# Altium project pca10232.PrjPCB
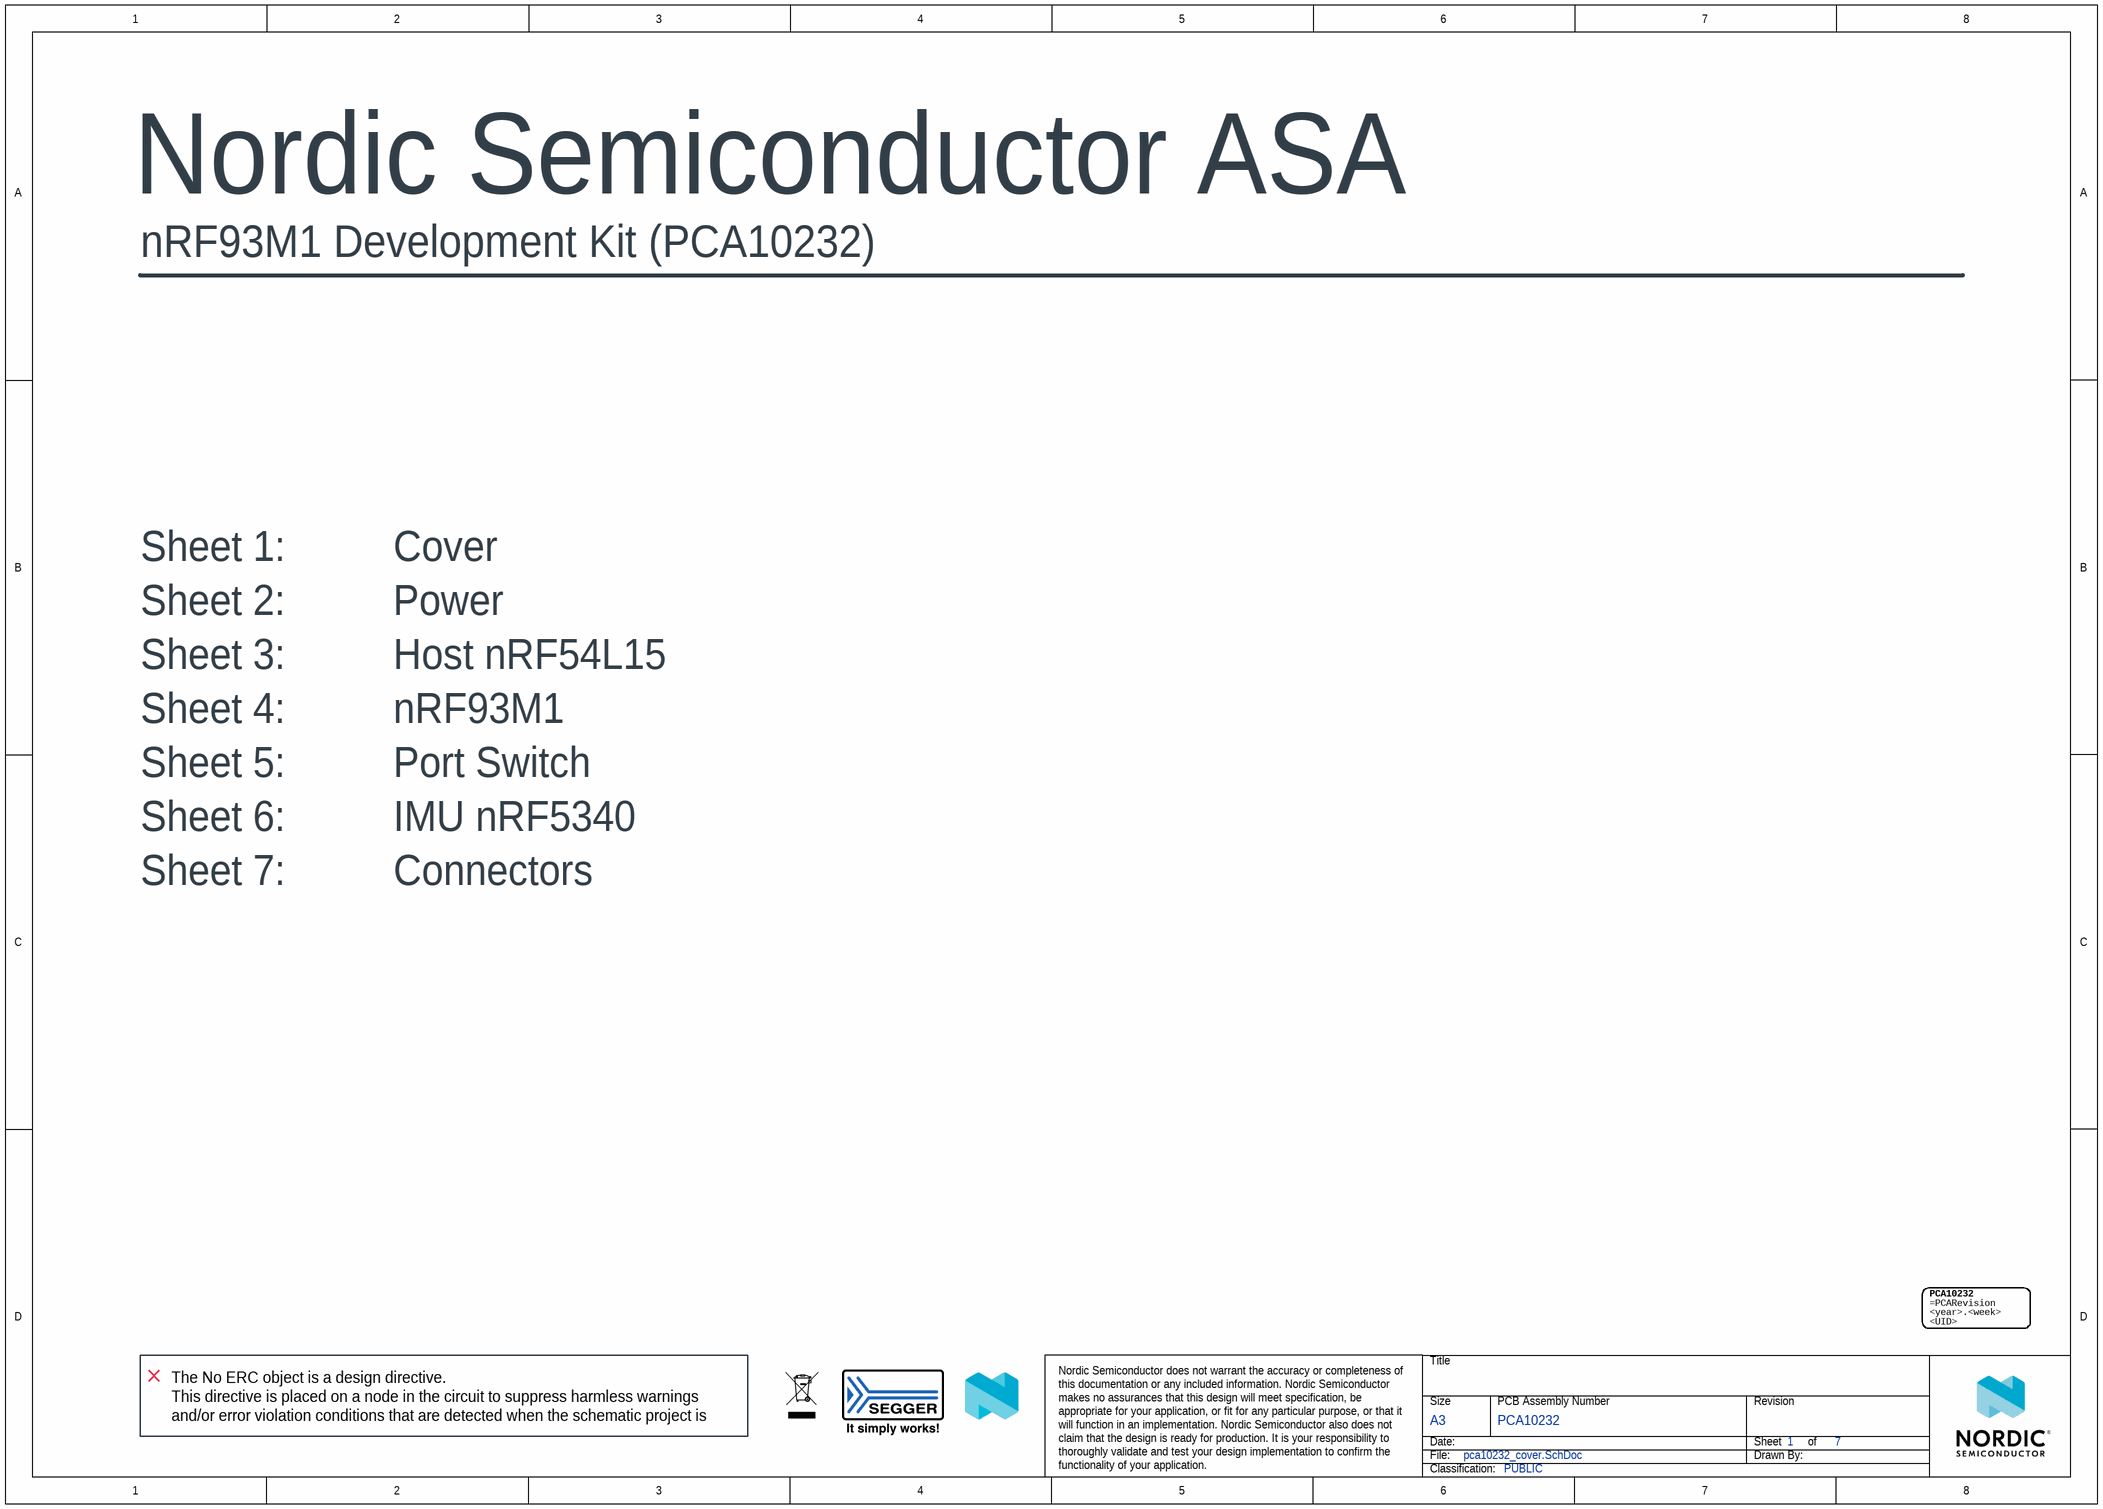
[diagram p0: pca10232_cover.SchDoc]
BoardThickness: 1.6mm; BoardTitle: nRF93M1 Development Kit; Classification: PUBLIC; Compliance: RoHS, REACH, Halogen-Free; Designer: Nordic Semiconductor; Dielectric: FR-4; NrOfLayers: 6; Organization: Nordic Semiconductor; PCAName: PCA10232; PCARevision: 0.4.0; PCBNumber: 401074; PCBRevision: 0.4.0; PCBStackup: 6001; ProductName: nRF93M1 Development Kit; ProjectName: nRF93M1; SilkscreenColor: White; SoldermaskColor: Blue; SurfaceFinish: ENIG Gold
7 sheets, 241 parts. Net scope: flat (ports and power ports of the same name join across sheets).
Board file: 401074.PcbDoc
Sheets:
  pca10232_cover.SchDoc
  pca10232_power.SchDoc
  pca10232_host_nrf54l15.SchDoc
  pca10232_nrf93m1.SchDoc
  pca10232_port_switch.SchDoc
  pca10232_imu_nrf5340.SchDoc
  pca10232_connectors.SchDoc

## Sheet pca10232_cover.SchDoc: =BoardTitle + ' - Cover'
size A3; Organization: Nordic Semiconductor; DocumentNumber: 1; Revision: 0.4.0; SheetNumber: 1; SheetTotal: 7; Author: Nordic Semiconductor; CompanyName: Nordic Semiconductor; DrawnBy: Nordic Semiconductor; DocumentSize: A3

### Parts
LABEL1  Solderbridge  [LabelSilk_15x40]  (value not drawn)  (graphical)
LOGO1  WEE Symbol  [WEEE_3x4.5mm]  (value not drawn)  (no BOM)
LOGO2  Segger Logo S  [logo]  (value not drawn)  (no BOM)
LOGO3  Solderbridge  [NORDIC_LOGO_LYING]  (value not drawn)  (graphical)

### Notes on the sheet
- Sheet 1:          Cover
- Sheet 2:          Power
- Sheet 3:          Host nRF54L15
- Sheet 4:          nRF93M1
- Sheet 5:          Port Switch
- Sheet 6:          IMU nRF5340
- Sheet 7:          Connectors
- The No ERC object is a design directive.
  This directive is placed on a node in the circuit to suppress harmless warnings and/or error violation conditions that are detected when the schematic project is compiled.

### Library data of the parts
LABEL1 = Label_15x40: PCA version label, stick-on, 15x40mm
LOGO1 = WEEE Symbol 3x4.5mm: WEEE Directive symbol; Manufacturer: N.A.
LOGO2 = Segger Logo S: Segger logo, small size; Manufacturer: N.A.
LOGO3 = Nordic Logo lying

## Sheet pca10232_power.SchDoc: =BoardTitle + ' - Power'
size A3; Organization: Nordic Semiconductor; DocumentNumber: 2; Revision: 0.4.0; SheetNumber: 2; SheetTotal: 7; Author: Nordic Semiconductor; CompanyName: Nordic Semiconductor; DrawnBy: Nordic Semiconductor; DocumentSize: A3
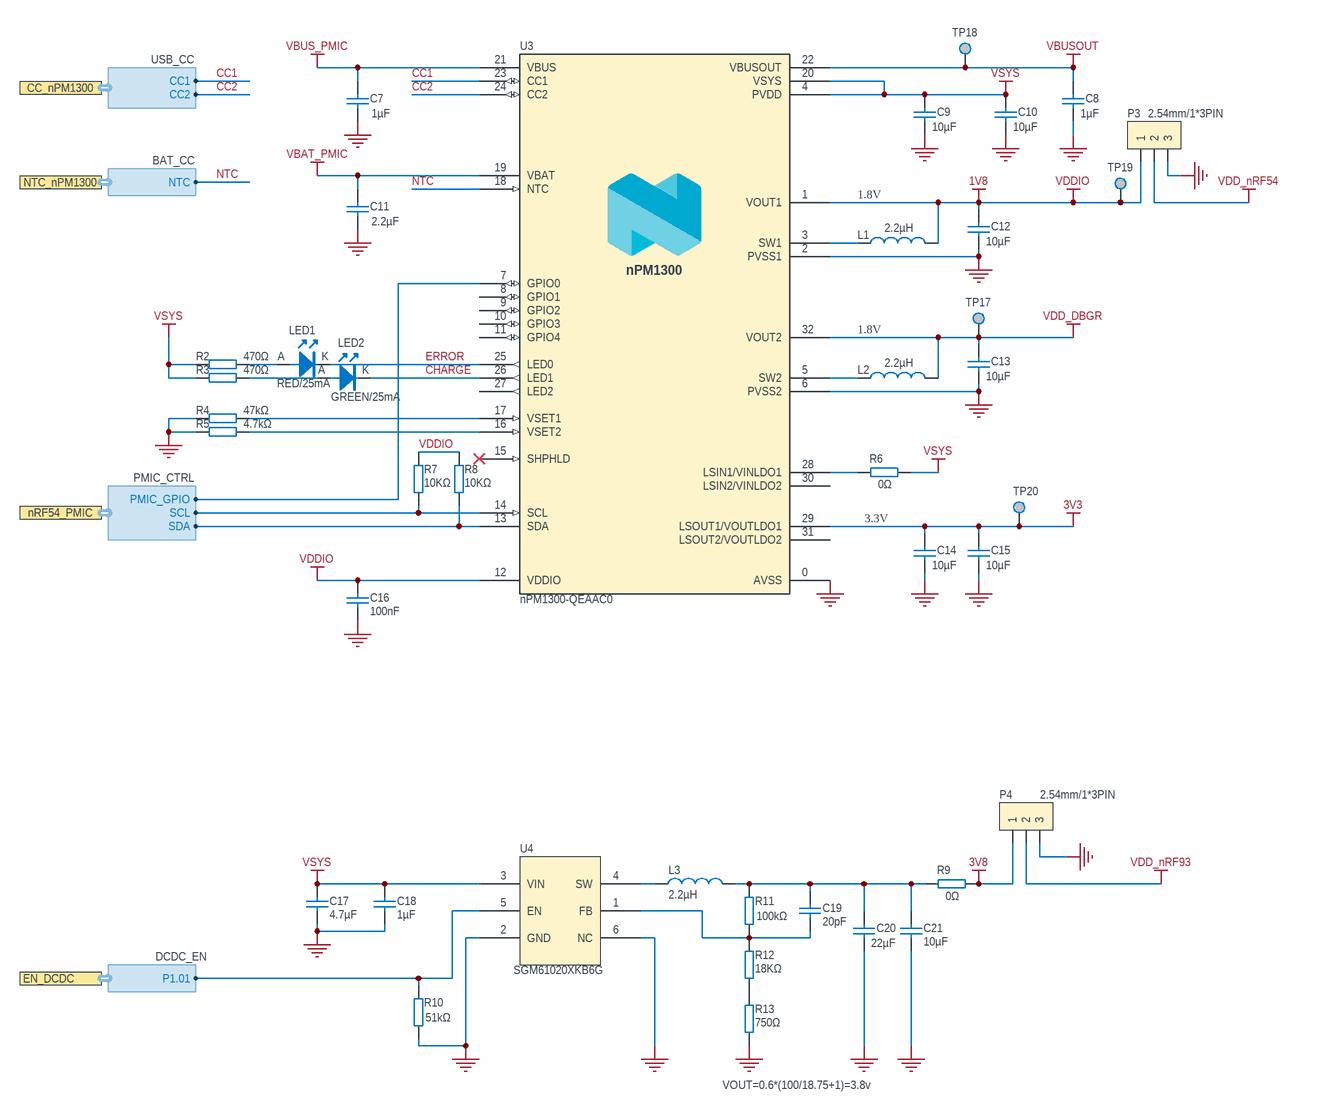
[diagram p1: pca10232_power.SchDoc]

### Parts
C7  1µF  [0402C_0.4D]
C8  1µF  [0402C_0.4D]
C9  10µF  [0603C_0.6D]
C10  10µF  [0603C_0.6D]
C11  2.2µF  [0402C_0.4D]
C12  10µF  [0603C_0.6D]
C13  10µF  [0603C_0.6D]
C14  10µF  [0603C_0.6D]
C15  10µF  [0603C_0.6D]
C16  100nF  [0201_0.25D]
C17  4.7µF  [0402C_0.4D]
C18  1µF  [0402C_0.4D]
C19  20pF  [0201_0.25D]
C20  22µF  [0603C_0.6D]
C21  10µF  [0402C_0.4D]
L1  2.2µH  [SKFB160808-2R2M]
L2  2.2µH  [SKFB160808-2R2M]
L3  2.2µH  [0805L_0.7D-NB]
LED1  RED/25mA  [D0402]
LED2  GREEN/25mA  [D0402]
P3  2.54mm/1*3PIN  [SIP 2.54_3_S]
P4  2.54mm/1*3PIN  [SIP 2.54_3_S]
R2  470Ω  [0402R_0.4D]
R3  470Ω  [0402R_0.4D]
R4  47kΩ  [0201_0.25D]
R5  4.7kΩ  [0201_0.25D]
R6  0Ω  [0402R_0.4D]
R7  10KΩ  [0201_0.25D]
R8  10KΩ  [0201_0.25D]
R9  0Ω  [0402R_0.4D]
R10  51kΩ  [0201_0.25D]
R11  100kΩ  [0201_0.25D]
R12  18KΩ  [0201_0.25D]
R13  750Ω  [0201_0.25D]
TP17  Testpoint  [test]  (value not drawn)  (no BOM)
TP18  Testpoint  [test]  (value not drawn)  (no BOM)
TP19  Testpoint  [test]  (value not drawn)  (no BOM)
TP20  Testpoint  [test]  (value not drawn)  (no BOM)
U3  nPM1300-QEAAC0  [QFN32(0.5)-5X5]
U4  SGM61020XKB6G  [SOT-563-6]

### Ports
CC_nPM1300 (harness USB_CC), EN_DCDC (harness DCDC_EN), nRF54_PMIC (harness PMIC_CTRL), NTC_nPM1300 (harness BAT_CC)

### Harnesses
USB_CC: CC1, CC2
BAT_CC: NTC
DCDC_EN: P1.01
PMIC_CTRL: SCL, SDA, PMIC_GPIO

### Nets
1V8: C12.2 C16.2 L1.2 P3.1 R7.2 R8.1 TP19.1 U3.1(VOUT1) U3.12(VDDIO)  [also labelled VDDIO]
3V3: C14.2 C15.2 TP20.1 U3.29(LSOUT1/VOUTLDO1)
3V8: P4.1 R9.2
GND: C7.1 C8.1 C9.1 C10.1 C11.1 C12.1 C13.1 C14.1 C15.1 C16.1 C17.1 C18.1 C20.1 C21.1 P3.3 P4.3 R4.1 R5.1 R10.1 R13.1 U3.0(AVSS) U3.2(PVSS1) U3.6(PVSS2) U4.2(GND) U4.6(NC)
VBAT_PMIC: C11.2 U3.19(VBAT)
VBUS_PMIC: C7.2 U3.21(VBUS)
VBUSOUT: C8.2 TP18.1 U3.22(VBUSOUT)
VDD_DBGR: C13.2 L2.2 TP17.1 U3.32(VOUT2)
VDD_nRF54: P3.2
VDD_nRF93: P4.2
VSYS: C9.2 C10.2 C17.2 C18.2 R2.1 R3.1 R6.2 U3.4(PVDD) U3.20(VSYS) U4.3(VIN)
CC1: U3.23(CC1) ; port CC_nPM1300.CC1
CC2: U3.24(CC2) ; port CC_nPM1300.CC2
CHARGE: LED2.K U3.26(LED1)
ERROR: LED1.K U3.25(LED0)
NTC: U3.18(NTC) ; port NTC_nPM1300.NTC
P1.01/XL2: R10.2 U4.5(EN) ; port EN_DCDC.P1.01
P1.11: R7.1 U3.14(SCL) ; port nRF54_PMIC.SCL
P1.14: R8.2 U3.13(SDA) ; port nRF54_PMIC.SDA
NetC19_1: C19.1 R11.1 R12.2 U4.1(FB)
NetC19_2: C19.2 C20.2 C21.2 L3.2 R9.1 R11.2
NetL1_1: L1.1 U3.3(SW1)
NetL2_1: L2.1 U3.5(SW2)
NetL3_1: L3.1 U4.4(SW)
NetLED1_A: LED1.A R2.2
NetLED2_A: LED2.A R3.2
NetR4_2: R4.2 U3.17(VSET1)
NetR5_2: R5.2 U3.16(VSET2)
NetR6_1: R6.1 U3.28(LSIN1/VINLDO1)
NetR12_1: R12.1 R13.2
NetSB3_2: U3.7(GPIO0) ; port nRF54_PMIC.PMIC_GPIO

Not connected (* = marked no-connect by the designer): U3 8(GPIO1) 9(GPIO2) 10(GPIO3) 11(GPIO4) 15(SHPHLD)* 27(LED2) 30(LSIN2/VINLDO2) 31(LSOUT2/VOUTLDO2)

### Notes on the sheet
- (near L1) 1.8V
- (near L2) 1.8V
- 3.3V
- (near R13) VOUT=0.6*(100/18.75+1)=3.8v

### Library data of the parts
C7 C8 = 1405002135: 1uF/25V/10%/X5R; Manufacturer Part Number: CL05A105KA5NQNC; Manufacturer: Samsung
C9 C10 C12-C15 = 1405005588: 10uF/25V/20%/X5R; Manufacturer Part Number: CC0603MRX5R8BB106; Manufacturer: Yageo
C11 = 1405005857: 2.2uF/16V/10%/X5R; Manufacturer Part Number: V225K0402X5R160NNT; Manufacturer: Viiyong
C16 = 1405001080: 0.1uF/10V/10%/X5R; Manufacturer Part Number: 0201X104K100CT; Manufacturer: Walsin
C17 = 1405002483: 4.7uF/16V/20%/X5R; Manufacturer Part Number: CL05A475MO5NUNC; Manufacturer: Samsung
C18 = 1405004038: 1uF/16V/10%/X5R; Manufacturer Part Number: CL05A105KO5NNNC; Manufacturer: Samsung
C19 = 1405004304: 20pF/50V/5%/C0G; Manufacturer Part Number: V200J0201C0G500NAT; Manufacturer: Viiyong
C20 = 1405001346: 22uF/10V/20%/X5R; Manufacturer Part Number: CL10A226MP8NUN#; Manufacturer: Samsung
C21 = 1405001308: 10uF/10V/20%/X5R; Manufacturer Part Number: CL05A106MP5NUNC; Manufacturer: Samsung
L1 L2 = 1404000234: 2.2uH/20%/2.5*2*1.2/2.07A/0.166Ω; Manufacturer Part Number: SWPA252012S2R2MT; Manufacturer: Sunlord
L3 = 1404002926: 2.2uH/20%/2.0*1.2*0.8/1.7A/146mΩ; Manufacturer Part Number: SKFB201208PA2R2M; Manufacturer: Scientic
LED1 = 1409000384: 25mA/40mcd; Manufacturer Part Number: 16-213SURC/S530-A3/TR8; Manufacturer: Everlight
LED2 = 1409003070: 25mA/112-225mcd; Manufacturer Part Number: 16-213/GHC-YR1S1N/3T; Manufacturer: Everlight
P3 P4 = 1416001241: Manufacturer Part Number: CNT-M254-1*3-GS-6/3-01
R2 R3 = 1408000316: 470Ω/5%; Manufacturer Part Number: RC0402JR-07470RL; Manufacturer: Yageo
R4 = 1408001835: 47KΩ/1%; Manufacturer Part Number: RC0201FR-0747KL; Manufacturer: Yageo
R5 = 1408002588: 4.7KΩ/1%; Manufacturer Part Number: 0201WMF4701TEE; Manufacturer: Uniohm
R6 R9 = 1408001258: 0Ω/1%; Manufacturer Part Number: RC0402FR-070RL; Manufacturer: Yageo
R7 R8 = 1408001391: 10KΩ/1%; Manufacturer Part Number: RC0201FR-0710KL; Manufacturer: Yageo
R10 = 1408006147: 51K/5%; Manufacturer Part Number: RJ0201-51K; Manufacturer: Uniohm
R11 = 1408002571: 100KΩ/1%; Manufacturer Part Number: 0201WMF1003TEE; Manufacturer: Uniohm
R12 = 1408006619: 18KΩ/1%; Manufacturer Part Number: RC0201FR-0718KL; Manufacturer: Yageo
R13 = 1408006619_1: 750Ω/1%; Manufacturer: Yageo
TP17-TP20 = MARK: Manufacturer Part Number: N.A.
U3 = nPM1300-QEAAC0: Li-Ion/Li-Polymer USB-C battery charger with high efficiency buck regulators, LDOs or load switches, LED drivers, TWI and VBUSOUT; Manufacturer: Nordic Semiconductor
U4 = SGM61020XKB6G/TR: Manufacturer: SG Micro

## Sheet pca10232_host_nrf54l15.SchDoc: =BoardTitle + ' - Host nRF54L15'
size A3; Organization: Nordic Semiconductor; DocumentNumber: 3; Revision: 0.4.0; SheetNumber: 3; SheetTotal: 7; Author: Nordic Semiconductor; CompanyName: Nordic Semiconductor; DrawnBy: Nordic Semiconductor; DocumentSize: A3
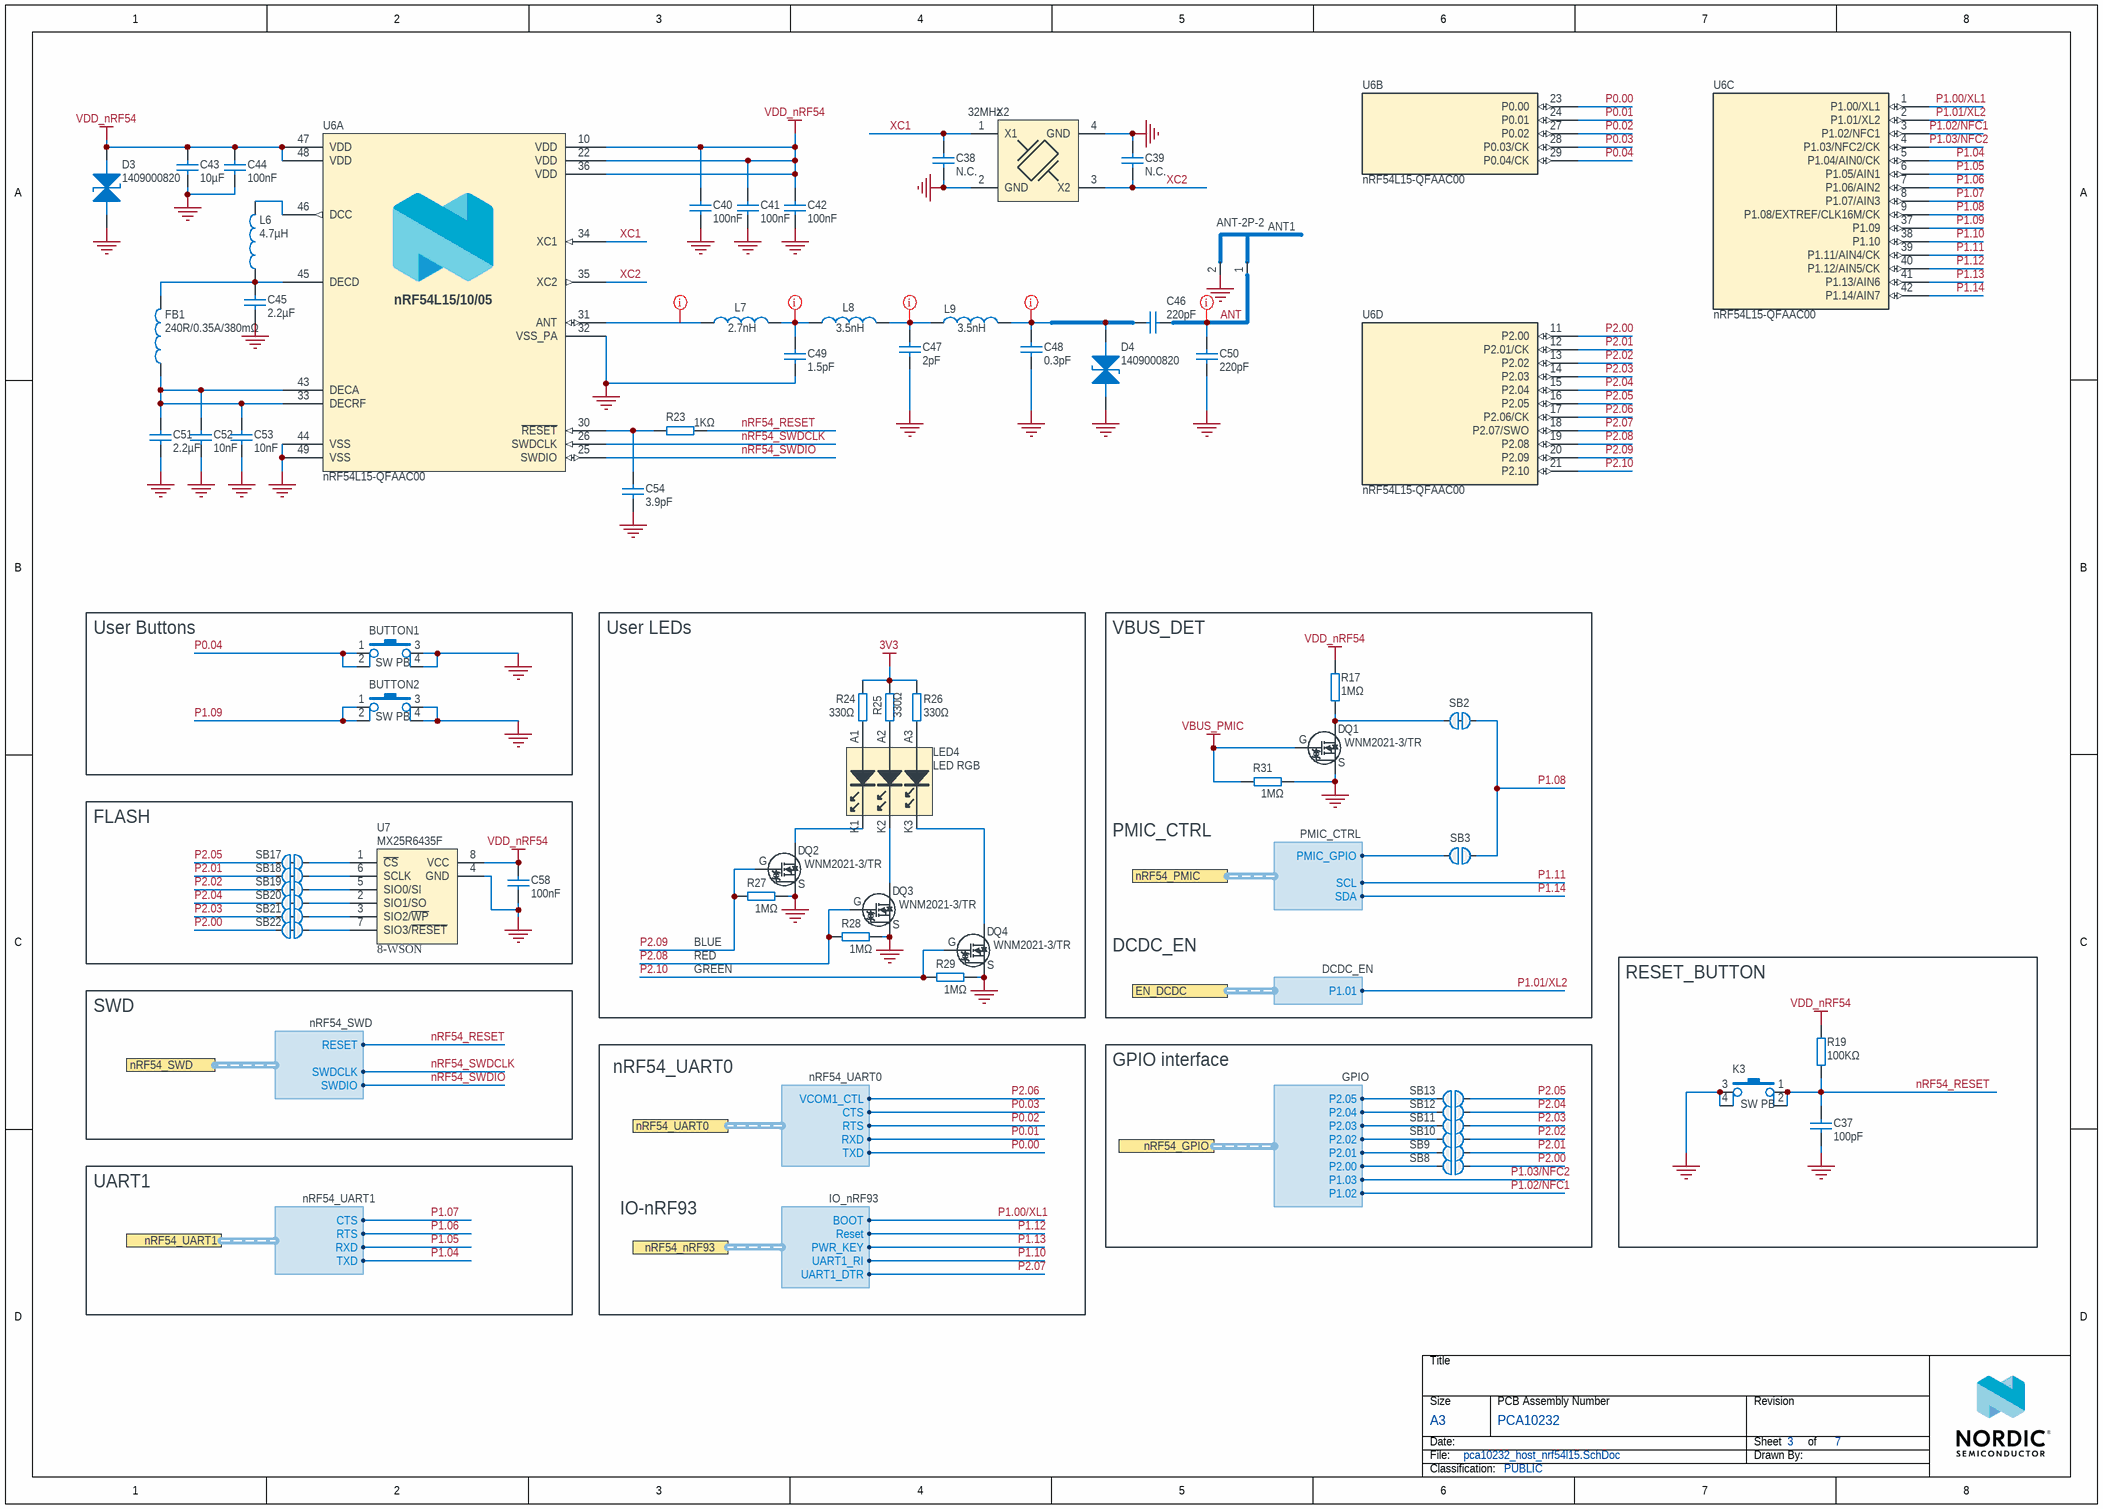
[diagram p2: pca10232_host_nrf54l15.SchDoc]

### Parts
ANT1  ANT-2P-2  [ANT_PCB]  (no BOM)
BUTTON1  SW PB  [SW-4.2X3.35-4P-S]
BUTTON2  SW PB  [SW-4.2X3.35-4P-S]
C37  100pF  [0402C_0.4D]
C38  N.C.  [0201_0.25D]
C39  N.C.  [0201_0.25D]
C40  100nF  [0201_0.25D]
C41  100nF  [0201_0.25D]
C42  100nF  [0201_0.25D]
C43  10µF  [0402C_0.4D-NB]
C44  100nF  [0201_0.25D]
C45  2.2µF  [0201_0.25D]
C46  220pF  [0201C_0.2D(NB)]
C47  2pF  [0201_0.25D]
C48  0.3pF  [0201_0.25D]
C49  1.5pF  [0201_0.25D]
C50  220pF  [0201C_0.2D(NB)]
C51  2.2µF  [0201_0.25D]
C52  10nF  [0201_0.25D]
C53  10nF  [0201_0.25D]
C54  3.9pF  [0201_0.25D]
C58  100nF  [0201_0.25D]
D3  1409000820  [DFN1006]
D4  1409000820  [D0201-NP]
FB1  240R/0.35A/380mΩ  [0201L_0.2D(NB)]
K3  SW PB  [SW-4.2X3.35-4P-S]
L6  4.7µH  [0603C_0.6D(RF)]
L7  2.7nH  [0201_0.25D]
L8  3.5nH  [0201_0.25D]
L9  3.5nH  [0201_0.25D]
LED4  LED RGB  [D1616-RGB]
Q1  WNM2021-3/TR  [SOT-323-3G]
Q2  WNM2021-3/TR  [SOT-323-3G]
Q3  WNM2021-3/TR  [SOT-323-3G]
Q4  WNM2021-3/TR  [SOT-323-3G]
R17  1MΩ  [0201_0.25D]
R19  100KΩ  [0201_0.25D]
R23  1KΩ  [0201_0.25D]
R24  330Ω  [0402R_0.4D]
R25  330Ω  [0402R_0.4D]
R26  330Ω  [0402R_0.4D]
R27  1MΩ  [0201_0.25D]
R28  1MΩ  [0201_0.25D]
R29  1MΩ  [0201_0.25D]
R31  1MΩ  [0201_0.25D]
SB2  Solderbridge_Shorted  [Solderbridge_Shorted]  (value not drawn)  (net tie, no BOM)
SB3  Solderbridge  [Solderbridge_NO_Shorted]  (value not drawn)  (no BOM)
SB8  Solderbridge  [Solderbridge_NO_Shorted]  (value not drawn)  (no BOM)
SB9  Solderbridge  [Solderbridge_NO_Shorted]  (value not drawn)  (no BOM)
SB10  Solderbridge  [Solderbridge_NO_Shorted]  (value not drawn)  (no BOM)
SB11  Solderbridge  [Solderbridge_NO_Shorted]  (value not drawn)  (no BOM)
SB12  Solderbridge  [Solderbridge_NO_Shorted]  (value not drawn)  (no BOM)
SB13  Solderbridge  [Solderbridge_NO_Shorted]  (value not drawn)  (no BOM)
SB17  Solderbridge_Shorted  [Solderbridge_Shorted]  (value not drawn)  (net tie, no BOM)
SB18  Solderbridge_Shorted  [Solderbridge_Shorted]  (value not drawn)  (net tie, no BOM)
SB19  Solderbridge_Shorted  [Solderbridge_Shorted]  (value not drawn)  (net tie, no BOM)
SB20  Solderbridge_Shorted  [Solderbridge_Shorted]  (value not drawn)  (net tie, no BOM)
SB21  Solderbridge_Shorted  [Solderbridge_Shorted]  (value not drawn)  (net tie, no BOM)
SB22  Solderbridge_Shorted  [Solderbridge_Shorted]  (value not drawn)  (net tie, no BOM)
U6  nRF54L15-QFAAC00  [nRF54L15_QFN48_6X6_0.4]  (parts A,B,C,D of 4)
U7  MX25R6435F  [WSON8L_6X5_1.27]
X2  32MHz  [2016]

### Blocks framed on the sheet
User Buttons: BUTTON1 BUTTON2
User LEDs: LED4 Q2-Q4 R24-R29
FLASH: C58 SB17-SB22 U7
RESET_BUTTON: C37 K3 R19
GPIO interface: SB8-SB13

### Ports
EN_DCDC (harness DCDC_EN), nRF54_GPIO (harness GPIO), nRF54_nRF93 (harness IO_nRF93), nRF54_PMIC (harness PMIC_CTRL), nRF54_SWD (harness nRF54_SWD), nRF54_UART0 (harness nRF54_UART0), nRF54_UART1 (harness nRF54_UART1)

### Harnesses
nRF54_SWD: SWDIO, SWDCLK, RESET
nRF54_UART0: RTS, CTS, RXD, TXD, VCOM1_CTL
nRF54_UART1: RTS, CTS, RXD, TXD
IO_nRF93: PWR_KEY, Reset, UART1_RI, UART1_DTR, BOOT
GPIO: P1.02, P1.03, P2.00, P2.01, P2.02, P2.03, P2.04, P2.05
PMIC_CTRL: SCL, SDA, PMIC_GPIO
DCDC_EN: P1.01

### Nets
3V3: R24.2 R25.2 R26.2
GND: ANT1.2 BUTTON1.3 BUTTON1.4 BUTTON2.3 BUTTON2.4 C37.1 C38.1 C39.2 C40.1 C41.1 C42.1 C43.1 C44.1 C45.1 C47.1 C48.1 C49.1 C50.1 C51.1 C52.1 C53.1 C54.1 C58.1 D3.A D4.A K3.3 K3.4 Q1.S Q2.S Q3.S Q4.S R27.2 R28.2 R29.2 R31.2 U6.32(VSS_PA) U6.44(VSS) U6.49(VSS) U7.4(GND) U7.9(GND) X2.2(GND) X2.4(GND)
VBUS_PMIC: Q1.G R31.1
VDD_nRF54: C40.2 C41.2 C42.2 C43.2 C44.2 C58.2 D3.K R17.2 R19.2 U6.10(VDD) U6.22(VDD) U6.36(VDD) U6.47(VDD) U6.48(VDD) U7.8(VCC)
ANT: ANT1.1 C46.2 C50.2
nRF54_RESET: C37.2 K3.1 K3.2 R19.1 R23.2 ; port nRF54_SWD.RESET
nRF54_SWDCLK: U6.26(SWDCLK) ; port nRF54_SWD.SWDCLK
nRF54_SWDIO: U6.25(SWDIO) ; port nRF54_SWD.SWDIO
P0.00: U6.23(P0.00) ; port nRF54_UART0.TXD
P0.01: U6.24(P0.01) ; port nRF54_UART0.RXD
P0.02: U6.27(P0.02) ; port nRF54_UART0.RTS
P0.03: U6.28(P0.03/CK) ; port nRF54_UART0.CTS
P0.04: BUTTON1.1 BUTTON1.2 U6.29(P0.04/CK)
P1.00/XL1: U6.1(P1.00/XL1) ; port nRF54_nRF93.BOOT  [project net BOOT]
P1.01/XL2: U6.2(P1.01/XL2) ; port EN_DCDC.P1.01
P1.02/NFC1: U6.3(P1.02/NFC1) ; port nRF54_GPIO.P1.02
P1.03/NFC2: U6.4(P1.03/NFC2/CK) ; port nRF54_GPIO.P1.03
P1.04: U6.5(P1.04/AIN0/CK) ; port nRF54_UART1.TXD
P1.05: U6.6(P1.05/AIN1) ; port nRF54_UART1.RXD
P1.06: U6.7(P1.06/AIN2) ; port nRF54_UART1.RTS
P1.07: U6.8(P1.07/AIN3) ; port nRF54_UART1.CTS
P1.08: SB2.2 SB3.1 U6.9(P1.08/EXTREF/CLK16M/CK)
P1.09: BUTTON2.1 BUTTON2.2 U6.37(P1.09)
P1.10: U6.38(P1.10) ; port nRF54_nRF93.UART1_RI
P1.11: U6.39(P1.11/AIN4/CK) ; port nRF54_PMIC.SCL
P1.12: U6.40(P1.12/AIN5/CK) ; port nRF54_nRF93.Reset
P1.13: U6.41(P1.13/AIN6) ; port nRF54_nRF93.PWR_KEY
P1.14: U6.42(P1.14/AIN7) ; port nRF54_PMIC.SDA
P2.00: SB8.2 SB22.1 U6.11(P2.00)
P2.01: SB9.2 SB18.1 U6.12(P2.01/CK)
P2.02: SB10.2 SB19.1 U6.13(P2.02)
P2.03: SB11.2 SB21.1 U6.14(P2.03)
P2.04: SB12.2 SB20.1 U6.15(P2.04)
P2.05: SB13.2 SB17.1 U6.16(P2.05)
P2.06: U6.17(P2.06/CK) ; port nRF54_UART0.VCOM1_CTL
P2.07: U6.18(P2.07/SWO) ; port nRF54_nRF93.UART1_DTR
P2.08: Q3.G R28.1 U6.19(P2.08)
P2.09: Q2.G R27.1 U6.20(P2.09)
P2.10: Q4.G R29.1 U6.21(P2.10)
XC1: C38.2 U6.34(XC1) X2.1(X1)
XC2: C39.1 U6.35(XC2) X2.3(X2)
NetC45_2: C45.2 FB1.2 L6.1 U6.45(DECD)
NetC46_1: C46.1 C48.2 D4.K L9.2
NetC47_2: C47.2 L8.2 L9.1
NetC49_2: C49.2 L7.2 L8.1
NetC51_2: C51.2 C52.2 C53.2 FB1.1 U6.33(DECRF) U6.43(DECA)
NetC54_2: C54.2 R23.1 U6.30(~{RESET})
NetL6_2: L6.2 U6.46(DCC)
NetL7_1: L7.1 U6.31(ANT)
NetLED4_A1: LED4.A1(A) R24.1
NetLED4_A2: LED4.A2(A) R25.1
NetLED4_A3: LED4.A3(A) R26.1
NetLED4_K1: LED4.K1(K) Q2.D
NetLED4_K2: LED4.K2(K) Q3.D
NetLED4_K3: LED4.K3(K) Q4.D
NetP1_5: SB8.1 ; port nRF54_GPIO.P2.00
NetP2_1: SB9.1 ; port nRF54_GPIO.P2.01
NetP2_2: SB10.1 ; port nRF54_GPIO.P2.02
NetP2_3: SB11.1 ; port nRF54_GPIO.P2.03
NetP2_4: SB12.1 ; port nRF54_GPIO.P2.04
NetP2_5: SB13.1 ; port nRF54_GPIO.P2.05
NetQ1_D: Q1.D R17.1 SB2.1
NetSB3_2: SB3.2 ; port nRF54_PMIC.PMIC_GPIO
NetSB17_2: SB17.2 U7.1(~{CS})
NetSB18_2: SB18.2 U7.6(SCLK)
NetSB19_2: SB19.2 U7.5(SIO0/SI)
NetSB20_2: SB20.2 U7.2(SIO1/SO)
NetSB21_2: SB21.2 U7.3(SIO2/~{WP})
NetSB22_2: SB22.2 U7.7(SIO3/~{RESET})

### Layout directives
net class ANT1: ANT, NetC46_1, NetC47_2, NetC49_2, NetL7_1

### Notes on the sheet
- VBUS_DET
- PMIC_CTRL
- (near U7) 8-WSON
- BLUE
- RED
- GREEN
- DCDC_EN
- SWD
- nRF54_UART0
- UART1
- IO-nRF93

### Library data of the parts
ANT1 = ANT 2P-2: ANT
BUTTON1 BUTTON2 K3 = 1414000721: 3.2*4.2*2.5mm; Manufacturer Part Number: BL-QC-3.2X4.2
C37 = 1405000464: 100pF/16V/10%/X7R; Manufacturer Part Number: CL05B104KO5NNNC; Manufacturer: Samsung
C38 C39 = CAP-NBOM: Manufacturer Part Number: N.A.
C40-C42 C44 C58 = 1405001080: as C16 on sheet pca10232_power
C43 = 1405001308_1: 10uF/10V/20%/X5R; Manufacturer Part Number: CL05A106MP5NUNC; Manufacturer: Samsung
C45 C51 = 1405005059: 2.2uF/10V/20%/X5R; Manufacturer Part Number: V225M0201X5R100NXT; Manufacturer: Viiyong
C46 C50 = 1405002000: 8pF/50V/0.1pF/C0G; Manufacturer Part Number: GRM0335C1H8R0BA01D; Manufacturer: Murata
C47 = 1405002405: 2pF/50V/±0.1pF/GQC; Manufacturer Part Number: V2R0B0201GQC500NAT; Manufacturer: Viiyong
C48 = 1405001154: 0.3pF/50V/±0.1pF/GQC; Manufacturer Part Number: V0R3B0201GQC500NAT; Manufacturer: Viiyong
C49 = 1405002406: 1.5pF/50V/±0.1pF/GQC; Manufacturer Part Number: V1R5B0201GQC500NAT; Manufacturer: Viiyong
C52 C53 = 1405005868: 10nF/25V/10%/X7R; Manufacturer Part Number: V103K0201X7R250NAT; Manufacturer: Viiyong
C54 = 1405002488: 3.9pF/50V/±0.1pF/C0G; Manufacturer Part Number: V3R9B0201C0G500NAT; Manufacturer: Viiyong
D3 = 1409000820_1: 5V/100W
D4 = 1409000820: 5V/100W
FB1 = 1404001917: Manufacturer: Murata
L6 = 1404000149: 0603
L7 = 1404002414: 2.7nH/±0.1nH/500mA/0.2Ω; Manufacturer Part Number: SDCL0603Q2N7BT02B03; Manufacturer: Sunlord
L8 L9 = 1404002487: 3.4nH/±0.1nH/450mA/0.25Ω; Manufacturer Part Number: SDCL0603Q3N4BT02B03; Manufacturer: Sunlord
LED4 = 1409000550: 25mA/100mcd,180mcd, 50mcd; Manufacturer Part Number: 19-337/R6GHBHC-A01/2T; Manufacturer: Everlight
Q1-Q4 = 1412002244: NMOS/20V/0.89A; Manufacturer: Willsemi
R17 R27-R29 R31 = 1408001480: 1MΩ/1%; Manufacturer Part Number: RC0201FR-071ML; Manufacturer: Yageo
R19 = 1408001446: 100KΩ/5%; Manufacturer Part Number: RC0201JR-07100KL; Manufacturer: Yageo
R23 = 1408001445: 1KΩ/5%; Manufacturer Part Number: RC0201JR-071KL; Manufacturer: Yageo
R24-R26 = 1408000315: 330Ω/5%; Manufacturer Part Number: 0402WGJ0331TCE; Manufacturer: Uniohm
SB2 SB17-SB22 = Solderbridge Shorted 0.4mm: Shorted Solderbridge; Manufacturer: N.A.
SB3 SB8-SB13 = Solderbridge 0.4mm: Manufacturer: N.A.
U6 = nRF54L15-QFAAC00: Multi-protocol Bluetooth Low Energy, IEEE 802.15.4 and 2.4GHz proprietary Wireless MCU; Manufacturer: Nordic Semiconductor
U7 = MX25R6435FZNIL0: Ultra low power, 64M-bit, serial multi I/O flash memory; Manufacturer: Macronix
X2 = 1413001678: 8pF/32MHz/10PPM/-40~85℃; Manufacturer Part Number: 9S32000073

## Sheet pca10232_nrf93m1.SchDoc: =BoardTitle + ' - nRF93M1 Cat.1bis'
size A3; Organization: Nordic Semiconductor; DocumentNumber: 4; Revision: 0.4.0; SheetNumber: 4; SheetTotal: 7; Author: Nordic Semiconductor; CompanyName: Nordic Semiconductor; DrawnBy: Nordic Semiconductor; DocumentSize: A3
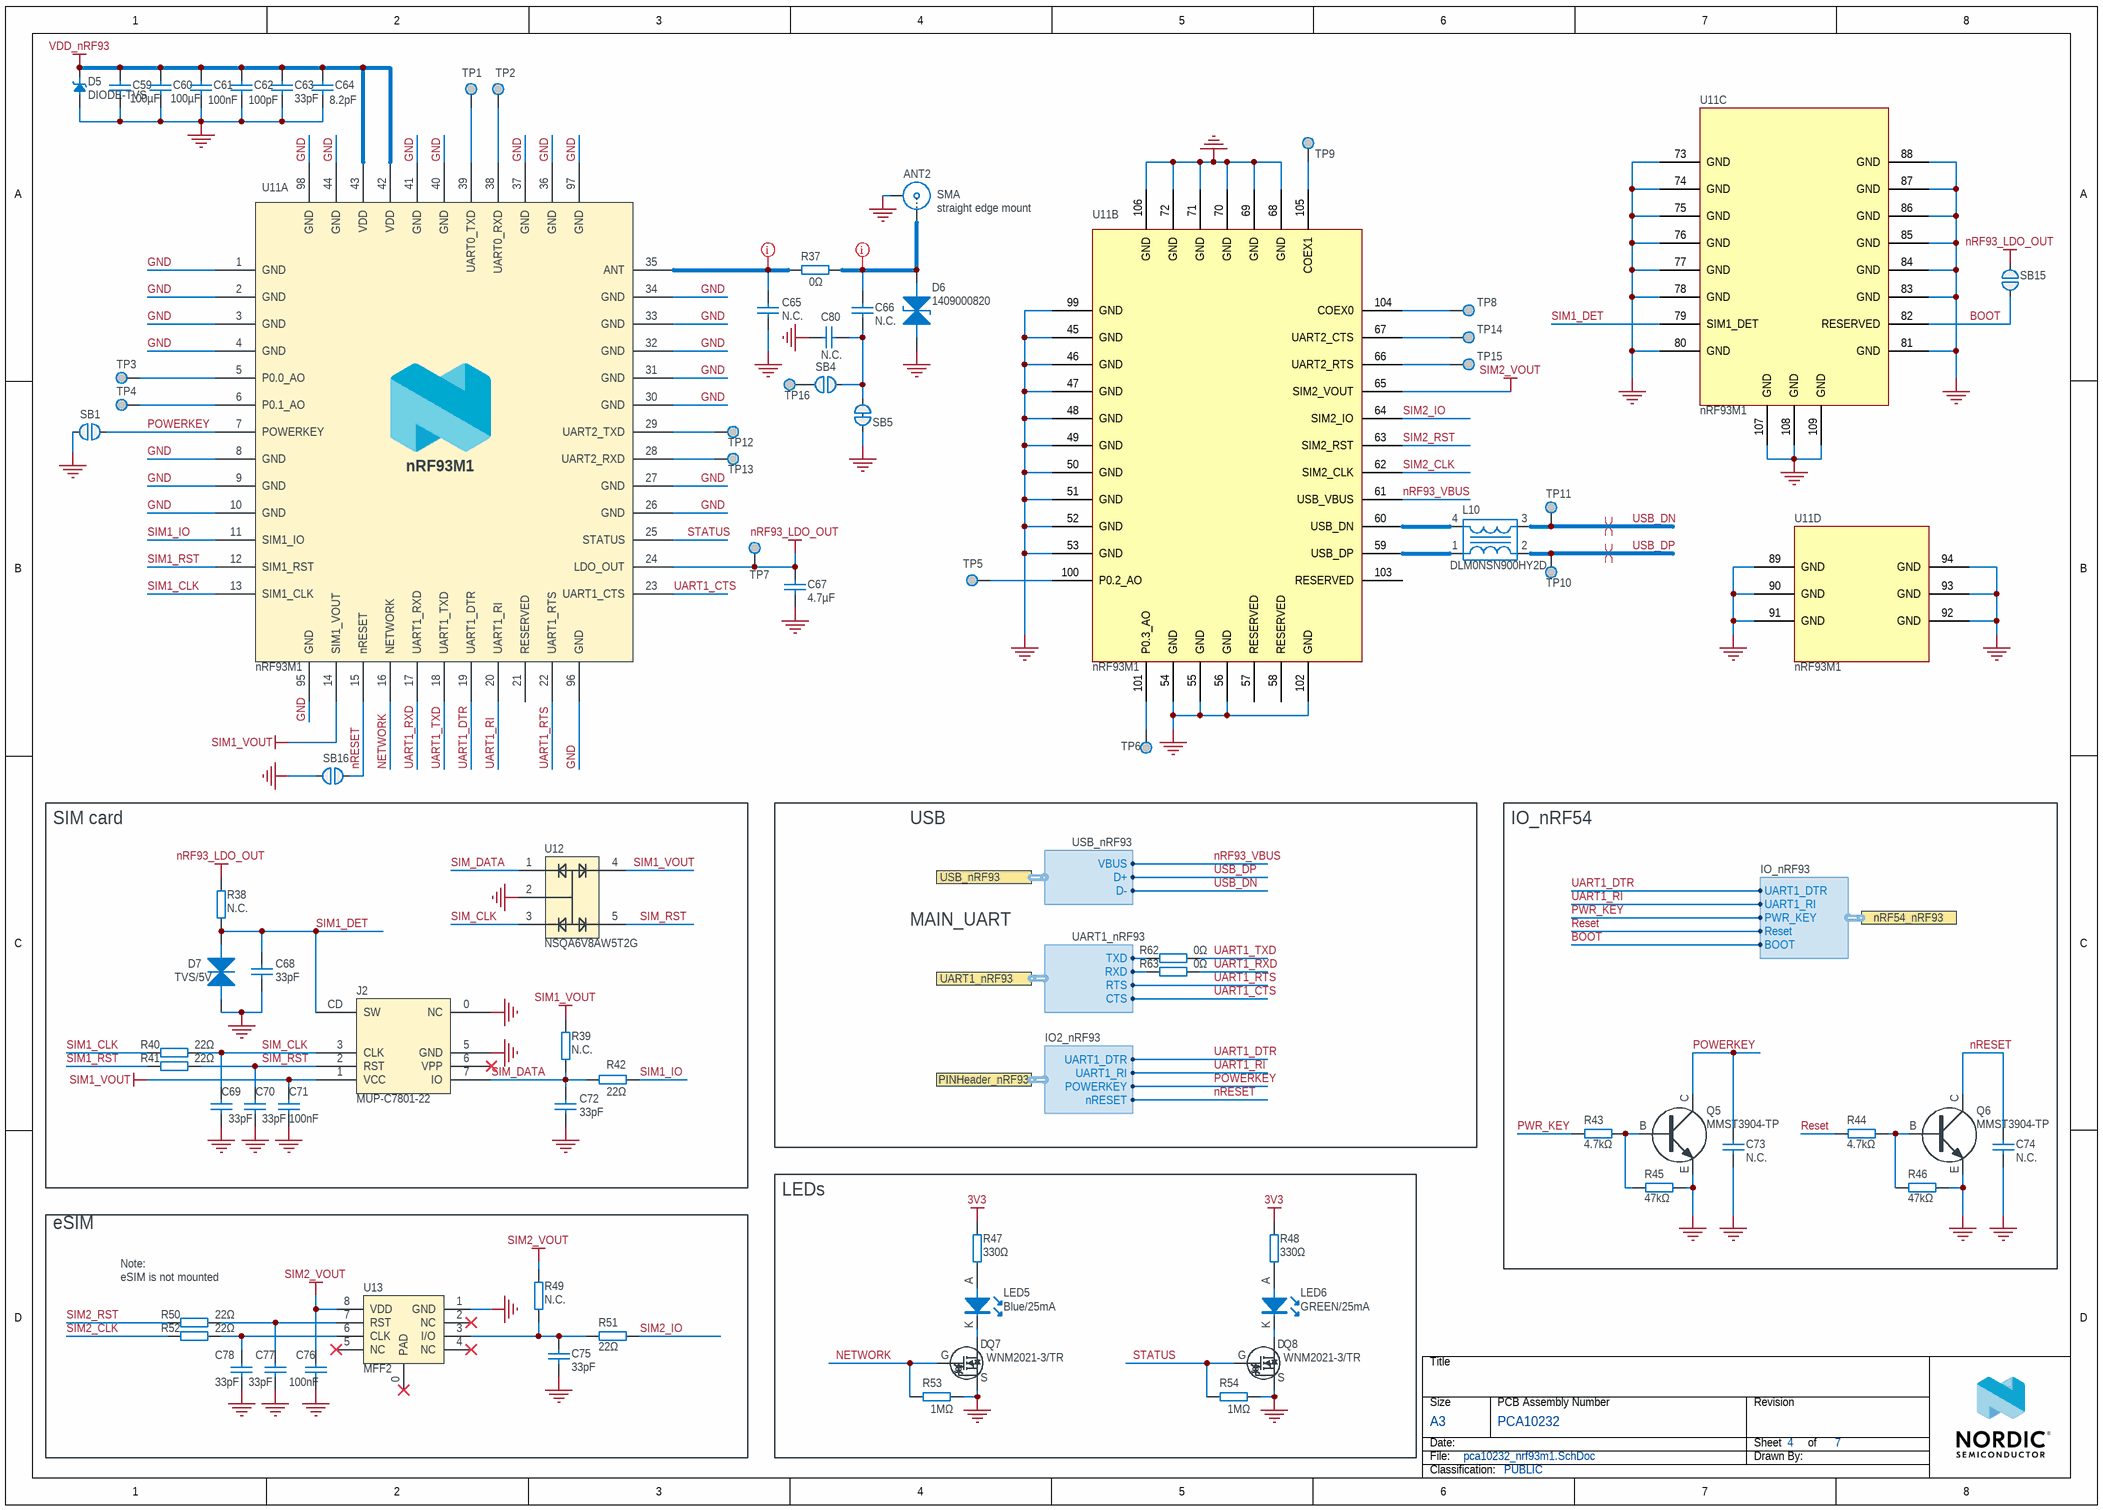
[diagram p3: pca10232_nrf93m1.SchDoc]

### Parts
ANT2  SMA  [SMA-SMD]
C59  100µF  [1206C_1.2D]
C60  100µF  [1206C_1.2D]
C61  100nF  [0201_0.25D]
C62  100pF  [0201_0.25D]
C63  33pF  [0201_0.25D]
C64  8.2pF  [0201_0.25D]
C65  N.C.  [0402C_0.4D]
C66  N.C.  [0402C_0.4D]
C67  4.7µF  [0201_0.25D]
C68  33pF  [0201_0.25D]
C69  33pF  [0201_0.25D]
C70  33pF  [0201_0.25D]
C71  100nF  [0201_0.25D]
C72  33pF  [0201_0.25D]
C73  N.C.  [0201_0.25D]
C74  N.C.  [0201_0.25D]
C75  33pF  [0201_0.25D]
C76  100nF  [0201_0.25D]
C77  33pF  [0201_0.25D]
C78  33pF  [0201_0.25D]
C80  N.C.  [0402C_0.4D]
D5  DIODE-TVS  [UDFN2(1610)]
D6  1409000820  [D0201-NP]
D7  TVS/5V  [SOD-523-NP]
J2  MUP-C7801-22  [SIM-MUP-C7801]
L10  DLM0NSN900HY2D  [L-0.85X0.65]
LED5  Blue/25mA  [D0402]
LED6  GREEN/25mA  [D0402]
Q5  MMST3904-TP  [SOT-323-3A]
Q6  MMST3904-TP  [SOT-323-3A]
Q7  WNM2021-3/TR  [SOT-323-3G]
Q8  WNM2021-3/TR  [SOT-323-3G]
R37  0Ω  [0402R_0.4D]
R38  N.C.  [0402R_0.4D]
R39  N.C.  [0201_0.25D]
R40  22Ω  [0201_0.25D]
R41  22Ω  [0201_0.25D]
R42  22Ω  [0201_0.25D]
R43  4.7kΩ  [0201_0.25D]
R44  4.7kΩ  [0201_0.25D]
R45  47kΩ  [0201_0.25D]
R46  47kΩ  [0201_0.25D]
R47  330Ω  [0402R_0.4D]
R48  330Ω  [0402R_0.4D]
R49  N.C.  [0201_0.25D]
R50  22Ω  [0201_0.25D]
R51  22Ω  [0201_0.25D]
R52  22Ω  [0201_0.25D]
R53  1MΩ  [0201_0.25D]
R54  1MΩ  [0201_0.25D]
R62  0Ω  [0402R_0.4D]
R63  0Ω  [0402R_0.4D]
SB1  Solderbridge  [Solderbridge_NO_Shorted]  (value not drawn)  (no BOM)
SB4  Solderbridge  [Solderbridge_NO_Shorted]  (value not drawn)  (no BOM)
SB5  Solderbridge_Shorted  [Solderbridge_Shorted]  (value not drawn)  (net tie, no BOM)
SB15  Solderbridge  [Solderbridge_NO_Shorted]  (value not drawn)  (no BOM)
SB16  Solderbridge  [Solderbridge_NO_Shorted]  (value not drawn)  (no BOM)
TP1  Testpoint  [test]  (value not drawn)  (no BOM)
TP2  Testpoint  [test]  (value not drawn)  (no BOM)
TP3  Testpoint  [test]  (value not drawn)  (no BOM)
TP4  Testpoint  [test]  (value not drawn)  (no BOM)
TP5  Testpoint  [test]  (value not drawn)  (no BOM)
TP6  Testpoint  [test]  (value not drawn)  (no BOM)
TP7  Testpoint  [test]  (value not drawn)  (no BOM)
TP8  Testpoint  [test]  (value not drawn)  (no BOM)
TP9  Testpoint  [test]  (value not drawn)  (no BOM)
TP10  Testpoint  [test]  (value not drawn)  (no BOM)
TP11  Testpoint  [test]  (value not drawn)  (no BOM)
TP12  Testpoint  [test]  (value not drawn)  (no BOM)
TP13  Testpoint  [test]  (value not drawn)  (no BOM)
TP14  Testpoint  [test]  (value not drawn)  (no BOM)
TP15  Testpoint  [test]  (value not drawn)  (no BOM)
TP16  Testpoint  [test]  (value not drawn)  (no BOM)
U11  nRF93M1  [nRF93M1]  (parts A,B,C,D of 4)
U12  NSQA6V8AW5T2G  [SOT-323-5]
U13  MFF2  [MFF2]

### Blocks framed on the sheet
SIM card: C68-C72 D7 J2 R38-R42 U12
IO_nRF54: C73 C74 Q5 Q6 R43-R46
LEDs: LED5 LED6 Q7 Q8 R47 R48 R53 R54
eSIM: C75-C78 R49-R52 U13

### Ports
nRF54_nRF93 (harness IO_nRF93), PINHeader_nRF93 (harness IO2_nRF93), UART1_nRF93 (harness UART1_nRF93), USB_nRF93 (harness USB_nRF93)

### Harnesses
USB_nRF93: D+, D-, VBUS
IO_nRF93: PWR_KEY, Reset, UART1_RI, UART1_DTR, BOOT
UART1_nRF93: RTS, CTS, TXD, RXD
IO2_nRF93: POWERKEY, nRESET, UART1_RI, UART1_DTR

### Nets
3V3: R47.2 R48.2
GND: ANT2.2(Y) C59.1 C60.1 C61.1 C62.1 C63.1 C64.1 C65.1 C67.1 C68.2 C69.1 C70.1 C71.1 C72.1 C73.1 C74.1 C75.1 C76.1 C77.1 C78.1 C80.2 D5.A D6.A D7.K J2.0(NC) J2.5(GND) Q5.E Q6.E Q7.S Q8.S R45.2 R46.2 R53.2 R54.2 SB1.1 SB5.1 SB16.1 U11.1(GND) U11.2(GND) U11.3(GND) U11.4(GND) U11.8(GND) U11.9(GND) U11.10(GND) U11.26(GND) U11.27(GND) U11.30(GND) U11.31(GND) U11.32(GND) U11.33(GND) U11.34(GND) U11.36(GND) U11.37(GND) U11.40(GND) U11.41(GND) U11.44(GND) U11.45(GND) U11.46(GND) U11.47(GND) U11.48(GND) U11.49(GND) U11.50(GND) U11.51(GND) U11.52(GND) U11.53(GND) U11.54(GND) U11.55(GND) U11.56(GND) U11.68(GND) U11.69(GND) U11.70(GND) U11.71(GND) U11.72(GND) U11.73(GND) U11.74(GND) U11.75(GND) U11.76(GND) U11.77(GND) U11.78(GND) U11.80(GND) U11.81(GND) U11.83(GND) U11.84(GND) U11.85(GND) U11.86(GND) U11.87(GND) U11.88(GND) U11.89(GND) U11.90(GND) U11.91(GND) U11.92(GND) U11.93(GND) U11.94(GND) U11.95(GND) U11.96(GND) U11.97(GND) U11.98(GND) U11.99(GND) U11.102(GND) U11.106(GND) U11.107(GND) U11.108(GND) U11.109(GND) U12.2 U13.1(GND)
nRF93_LDO_OUT: C67.2 R38.1 SB15.2 TP7.1 U11.24(LDO_OUT)
SIM1_VOUT: C71.2 J2.1(VCC) R39.2 U11.14(SIM1_VOUT) U12.4
SIM2_VOUT: C76.2 R49.2 U11.65(SIM2_VOUT) U13.8(VDD)
VDD_nRF93: C59.2 C60.2 C61.2 C62.2 C63.2 C64.2 D5.K U11.42(VDD) U11.43(VDD)
BOOT: SB15.1 U11.82(RESERVED) ; port nRF54_nRF93.BOOT
NETWORK: Q7.G R53.1 U11.16(NETWORK)
nRESET: C74.2 Q6.C SB16.2 U11.15(nRESET) ; port PINHeader_nRF93.nRESET
nRF93_VBUS: U11.61(USB_VBUS) ; port USB_nRF93.VBUS
POWERKEY: C73.2 Q5.C SB1.2 U11.7(POWERKEY) ; port PINHeader_nRF93.POWERKEY
PWR_KEY: R43.1 ; port nRF54_nRF93.PWR_KEY  [project net P1.13]
Reset: R44.1 ; port nRF54_nRF93.Reset  [project net P1.12]
SIM1_CLK: R40.1 U11.13(SIM1_CLK)
SIM1_DET: C68.1 D7.A J2.CD(SW) R38.2 U11.79(SIM1_DET)
SIM1_IO: R42.2 U11.11(SIM1_IO)
SIM1_RST: R41.1 U11.12(SIM1_RST)
SIM2_CLK: R52.2 U11.62(SIM2_CLK)
SIM2_IO: R51.1 U11.64(SIM2_IO)
SIM2_RST: R50.2 U11.63(SIM2_RST)
SIM_CLK: C69.2 J2.3(CLK) R40.2 U12.3
SIM_DATA: C72.2 J2.7(IO) R39.1 R42.1 U12.1
SIM_RST: C70.2 J2.2(RST) R41.2 U12.5
STATUS: Q8.G R54.1 U11.25(STATUS)
UART1_CTS: U11.23(UART1_CTS) ; port UART1_nRF93.CTS
UART1_DTR: U11.19(UART1_DTR) ; port nRF54_nRF93.UART1_DTR, port PINHeader_nRF93.UART1_DTR  [project net P2.07]
UART1_RI: U11.20(UART1_RI) ; port nRF54_nRF93.UART1_RI, port PINHeader_nRF93.UART1_RI  [project net P1.10]
UART1_RTS: U11.22(UART1_RTS) ; port UART1_nRF93.RTS
UART1_RXD: R63.2 U11.17(UART1_RXD)
UART1_TXD: R62.2 U11.18(UART1_TXD)
USB_DN: L10.3 TP11.1 ; port USB_nRF93.D-  [project net USB2_N]
USB_DP: L10.2 TP10.1 ; port USB_nRF93.D+  [project net USB2_P]
NetANT2_1: ANT2.1(X) C66.2 D6.K R37.2
NetC65_2: C65.2 R37.1 U11.35(ANT)
NetC66_1: C66.1 C80.1 SB4.2 SB5.2
NetC75_2: C75.2 R49.1 R51.2 U13.3(I/O)
NetC77_2: C77.2 R50.1 U13.7(RST)
NetC78_2: C78.2 R52.1 U13.6(CLK)
NetL10_1: L10.1 U11.59(USB_DP)
NetL10_4: L10.4 U11.60(USB_DN)
NetLED5_A: LED5.A R47.1
NetLED5_K: LED5.K Q7.D
NetLED6_A: LED6.A R48.1
NetLED6_K: LED6.K Q8.D
NetP5_1: R62.1 ; port UART1_nRF93.TXD
NetP5_2: R63.1 ; port UART1_nRF93.RXD
NetQ5_B: Q5.B R43.2 R45.1
NetQ6_B: Q6.B R44.2 R46.1
NetSB4_1: SB4.1 TP16.1
NetTP1_1: TP1.1 U11.39(UART0_TXD)
NetTP2_1: TP2.1 U11.38(UART0_RXD)
NetTP3_1: TP3.1 U11.5(P0.0_AO)
NetTP4_1: TP4.1 U11.6(P0.1_AO)
NetTP5_1: TP5.1 U11.100(P0.2_AO)
NetTP6_1: TP6.1 U11.101(P0.3_AO)
NetTP8_1: TP8.1 U11.104(COEX0)
NetTP9_1: TP9.1 U11.105(COEX1)
NetTP12_1: TP12.1 U11.29(UART2_TXD)
NetTP13_1: TP13.1 U11.28(UART2_RXD)
NetTP14_1: TP14.1 U11.67(UART2_CTS)
NetTP15_1: TP15.1 U11.66(UART2_RTS)

Not connected (* = marked no-connect by the designer): J2 6(VPP)*; U11 21(RESERVED) 57(RESERVED) 58(RESERVED) 103(RESERVED); U13 0(PAD)* 2(NC)* 4(NC)* 5(NC)*

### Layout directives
differential pair: USB2_N, USB2_P
net class ANT1: NetANT2_1, NetC65_2

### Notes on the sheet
- (near ANT2) straight edge mount
- (near U11) nRF93M1
- USB
- MAIN_UART
- Note:                             eSIM is not mounted

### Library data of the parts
ANT2 = SMA_EDGE: CON SMA RCPT STR 50OHM EDGE MNT; Manufacturer: SMA edge
C59 C60 = 1405002417: 100uF/6.3V/20%/X5R; Manufacturer Part Number: CL31A107MQHNNNE; Manufacturer: Samsung
C61 C71 C76 = 1405001272: 0.1uF/10V/10%/X5R; Manufacturer Part Number: V104K0201X5R100NAT; Manufacturer: Viiyong
C62 = 1405001363: 100pF/50V/5%/C0G; Manufacturer Part Number: V101J0201C0G500NAT; Manufacturer: Viiyong
C63 C68-C70 C72 C75 C77 C78 = 1405002411: 33pF/50V/5%/C0G; Manufacturer Part Number: V330J0201C0G500NAT; Manufacturer: Viiyong
C64 = 1405005275: 8.2pF/50V/±0.1pF/C0G; Manufacturer Part Number: CC0201BRNPO9BN8R2; Manufacturer: Yageo
C65 C66 C80 = 1405000291: 33pF/50V/5%/C0G; Manufacturer Part Number: CC0402JRNPO9BN330; Manufacturer: Yageo
C67 = 1405005345: 4.7uF/6.3V/20%/X5R; Manufacturer Part Number: CL03A475MQ5C65C; Manufacturer: Samsung
C73 C74 = CAP-NBOM: Manufacturer Part Number: N.A.
D5 = DIODE-TVS: 4.5V; Manufacturer Part Number: WS4.5DPVL; Manufacturer: Walsin
D6 = 1409000820: 5V/100W
D7 = 1409000207: ESD; Manufacturer: Nexperia
J2 = 1416003652: NANO SIM; Manufacturer: MUP
L10 = 1404002237: 90Ω/0.1A/3.8Ω; Manufacturer Part Number: DLM0NSM900HY2#; Manufacturer: Murata
LED5 = 1409000343: 25mA/28.5-72mcd; Manufacturer Part Number: 16-213/BHC-AN1P2/3T; Manufacturer: Everlight
LED6 = 1409003070: as LED2 on sheet pca10232_power
Q5 Q6 = 1412002759: NPN/200mA/40V/200mW; Manufacturer: MCC
Q7 Q8 = 1412002244: NMOS/20V/0.89A; Manufacturer: Willsemi
R37 = 1408001258: as R6 on sheet pca10232_power
R38 = 1408000158: 10K/5%; Manufacturer Part Number: RC0402JR-0710KL; Manufacturer: Yageo
R39 R49 = RES-NBOM_0201: Manufacturer Part Number: N.A.
R40-R42 R50-R52 = 1408001481: 22Ω/1%; Manufacturer Part Number: RC0201FR-0722RL; Manufacturer: Yageo
R43 R44 = 1408002588: as R5 on sheet pca10232_power
R45 R46 = 1408001835: as R4 on sheet pca10232_power
R47 R48 = 1408000315: as R24 on sheet pca10232_host_nrf54l15
R53 R54 = 1408001480: as R17 on sheet pca10232_host_nrf54l15
R62 R63 = 1408000461: 0Ω/5%; Manufacturer Part Number: RC0402JR-070RL; Manufacturer: Yageo
SB1 SB4 SB15 SB16 = Solderbridge: Manufacturer: N.A.
SB5 = Solderbridge Shorted 0.4mm: Shorted Solderbridge; Manufacturer: N.A.
TP1-TP16 = MARK: Manufacturer Part Number: N.A.
U11 = nRF93M1-LABA_V02: Manufacturer: Nordic Semiconductor
U12 = 1409000217: 7.14V/600W; Manufacturer: Onsemi
U13 = QUAD_EUICC

## Sheet pca10232_port_switch.SchDoc: =BoardTitle + ' - Port Switch'
size A3; Organization: Nordic Semiconductor; DocumentNumber: 5; Revision: 0.4.0; SheetNumber: 5; SheetTotal: 7; Author: Nordic Semiconductor; CompanyName: Nordic Semiconductor; DrawnBy: Nordic Semiconductor; DocumentSize: A3
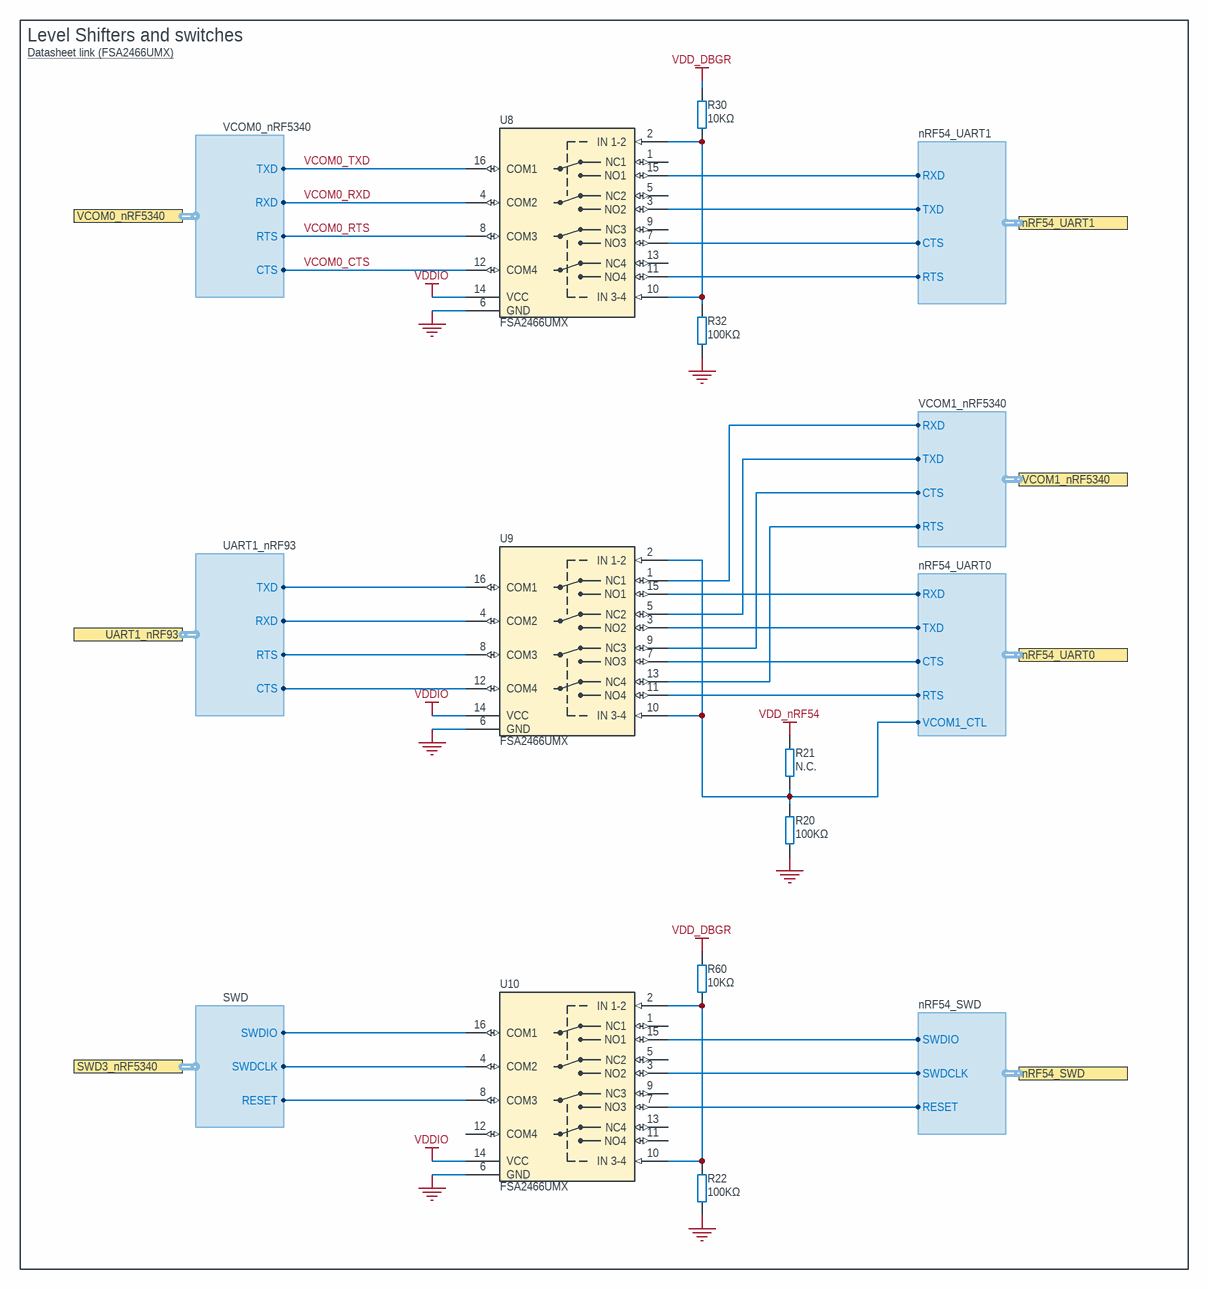
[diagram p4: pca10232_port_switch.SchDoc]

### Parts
R20  100KΩ  [0201_0.25D]
R21  N.C.  [0201_0.25D]
R22  100KΩ  [0201_0.25D]
R30  10KΩ  [0201_0.25D]
R32  100KΩ  [0201_0.25D]
R60  10KΩ  [0201_0.25D]
U8  FSA2466UMX  [FSA2466UMX_1.8x2.6_0.4]
U9  FSA2466UMX  [FSA2466UMX_1.8x2.6_0.4]
U10  FSA2466UMX  [FSA2466UMX_1.8x2.6_0.4]

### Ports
nRF54_SWD (harness nRF54_SWD), nRF54_UART0 (harness nRF54_UART0), nRF54_UART1 (harness nRF54_UART1), SWD3_nRF5340 (harness SWD), UART1_nRF93 (harness UART1_nRF93), VCOM0_nRF5340 (harness VCOM0_nRF5340), VCOM1_nRF5340 (harness VCOM1_nRF5340)

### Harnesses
VCOM0_nRF5340: RTS, CTS, RXD, TXD
nRF54_UART1: RTS, CTS, RXD, TXD
SWD: SWDIO, SWDCLK, RESET
nRF54_SWD: SWDIO, SWDCLK, RESET
nRF54_UART0: RTS, CTS, RXD, TXD, VCOM1_CTL
VCOM1_nRF5340: CTS, RTS, TXD, RXD
UART1_nRF93: RTS, CTS, TXD, RXD

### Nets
GND: R20.1 R22.2 R32.2 U8.6(GND) U9.6(GND) U10.6(GND)
VDD_DBGR: R30.2 R60.2
VDD_nRF54: R21.1
VDDIO: U8.14(VCC) U9.14(VCC) U10.14(VCC)  [project net 1V8]
nRF54_RESET: U10.7(NO3) ; port nRF54_SWD.RESET
nRF54_SWDCLK: U10.3(NO2) ; port nRF54_SWD.SWDCLK
nRF54_SWDIO: U10.15(NO1) ; port nRF54_SWD.SWDIO
P0.00: U9.3(NO2) ; port nRF54_UART0.TXD
P0.01: U9.15(NO1) ; port nRF54_UART0.RXD
P0.02: U9.11(NO4) ; port nRF54_UART0.RTS
P0.03: U9.7(NO3) ; port nRF54_UART0.CTS
P1.04: U8.3(NO2) ; port nRF54_UART1.TXD
P1.05: U8.15(NO1) ; port nRF54_UART1.RXD
P1.06: U8.11(NO4) ; port nRF54_UART1.RTS
P1.07: U8.7(NO3) ; port nRF54_UART1.CTS
P2.06: R20.2 R21.2 U9.2(IN_1-2) U9.10(IN_3-4) ; port nRF54_UART0.VCOM1_CTL
UART1_CTS: U9.12(COM4) ; port UART1_nRF93.CTS
UART1_RTS: U9.8(COM3) ; port UART1_nRF93.RTS
VCOM0_CTS: U8.12(COM4) ; port VCOM0_nRF5340.CTS
VCOM0_RTS: U8.8(COM3) ; port VCOM0_nRF5340.RTS
VCOM0_RXD: U8.4(COM2) ; port VCOM0_nRF5340.RXD
VCOM0_TXD: U8.16(COM1) ; port VCOM0_nRF5340.TXD
VCOM1_CTS: U9.9(NC3) ; port VCOM1_nRF5340.CTS
VCOM1_RTS: U9.13(NC4) ; port VCOM1_nRF5340.RTS
VCOM1_RXD: U9.1(NC1) ; port VCOM1_nRF5340.RXD
VCOM1_TXD: U9.5(NC2) ; port VCOM1_nRF5340.TXD
NetP5_1: U9.16(COM1) ; port UART1_nRF93.TXD
NetP5_2: U9.4(COM2) ; port UART1_nRF93.RXD
NetR14_2: U10.16(COM1) ; port SWD3_nRF5340.SWDIO
NetR16_2: U10.4(COM2) ; port SWD3_nRF5340.SWDCLK
NetR18_2: U10.8(COM3) ; port SWD3_nRF5340.RESET
NetR22_1: R22.1 R60.1 U10.2(IN_1-2) U10.10(IN_3-4)
NetR30_1: R30.1 R32.1 U8.2(IN_1-2) U8.10(IN_3-4)

Not connected (* = marked no-connect by the designer): U8 1(NC1) 5(NC2) 9(NC3) 13(NC4); U10 1(NC1) 5(NC2) 9(NC3) 11(NO4) 12(COM4) 13(NC4)

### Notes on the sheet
- Level Shifters and switches
- Datasheet link (FSA2466UMX) <https://www.onsemi.com/pdf/datasheet/fsa2466-d.pdf>

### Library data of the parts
R20 R22 R32 = 1408001446: as R19 on sheet pca10232_host_nrf54l15
R21 = RES-NBOM_0201: Manufacturer Part Number: N.A.
R30 R60 = 1408001444: 10KΩ/5%; Manufacturer Part Number: RC0201JR-0710KL; Manufacturer: Yageo
U8-U10 = FSA2466UMX: Data / Audio Low-Voltage Dual DPDT Analog Switch; Manufacturer: Onsemi

## Sheet pca10232_imu_nrf5340.SchDoc: =BoardTitle + ' - IMU nRF5340'
size A3; Organization: Nordic Semiconductor; DocumentNumber: 6; Revision: 0.4.0; SheetNumber: 6; SheetTotal: 7; Author: Nordic Semiconductor; CompanyName: Nordic Semiconductor; DrawnBy: Nordic Semiconductor; DocumentSize: A3
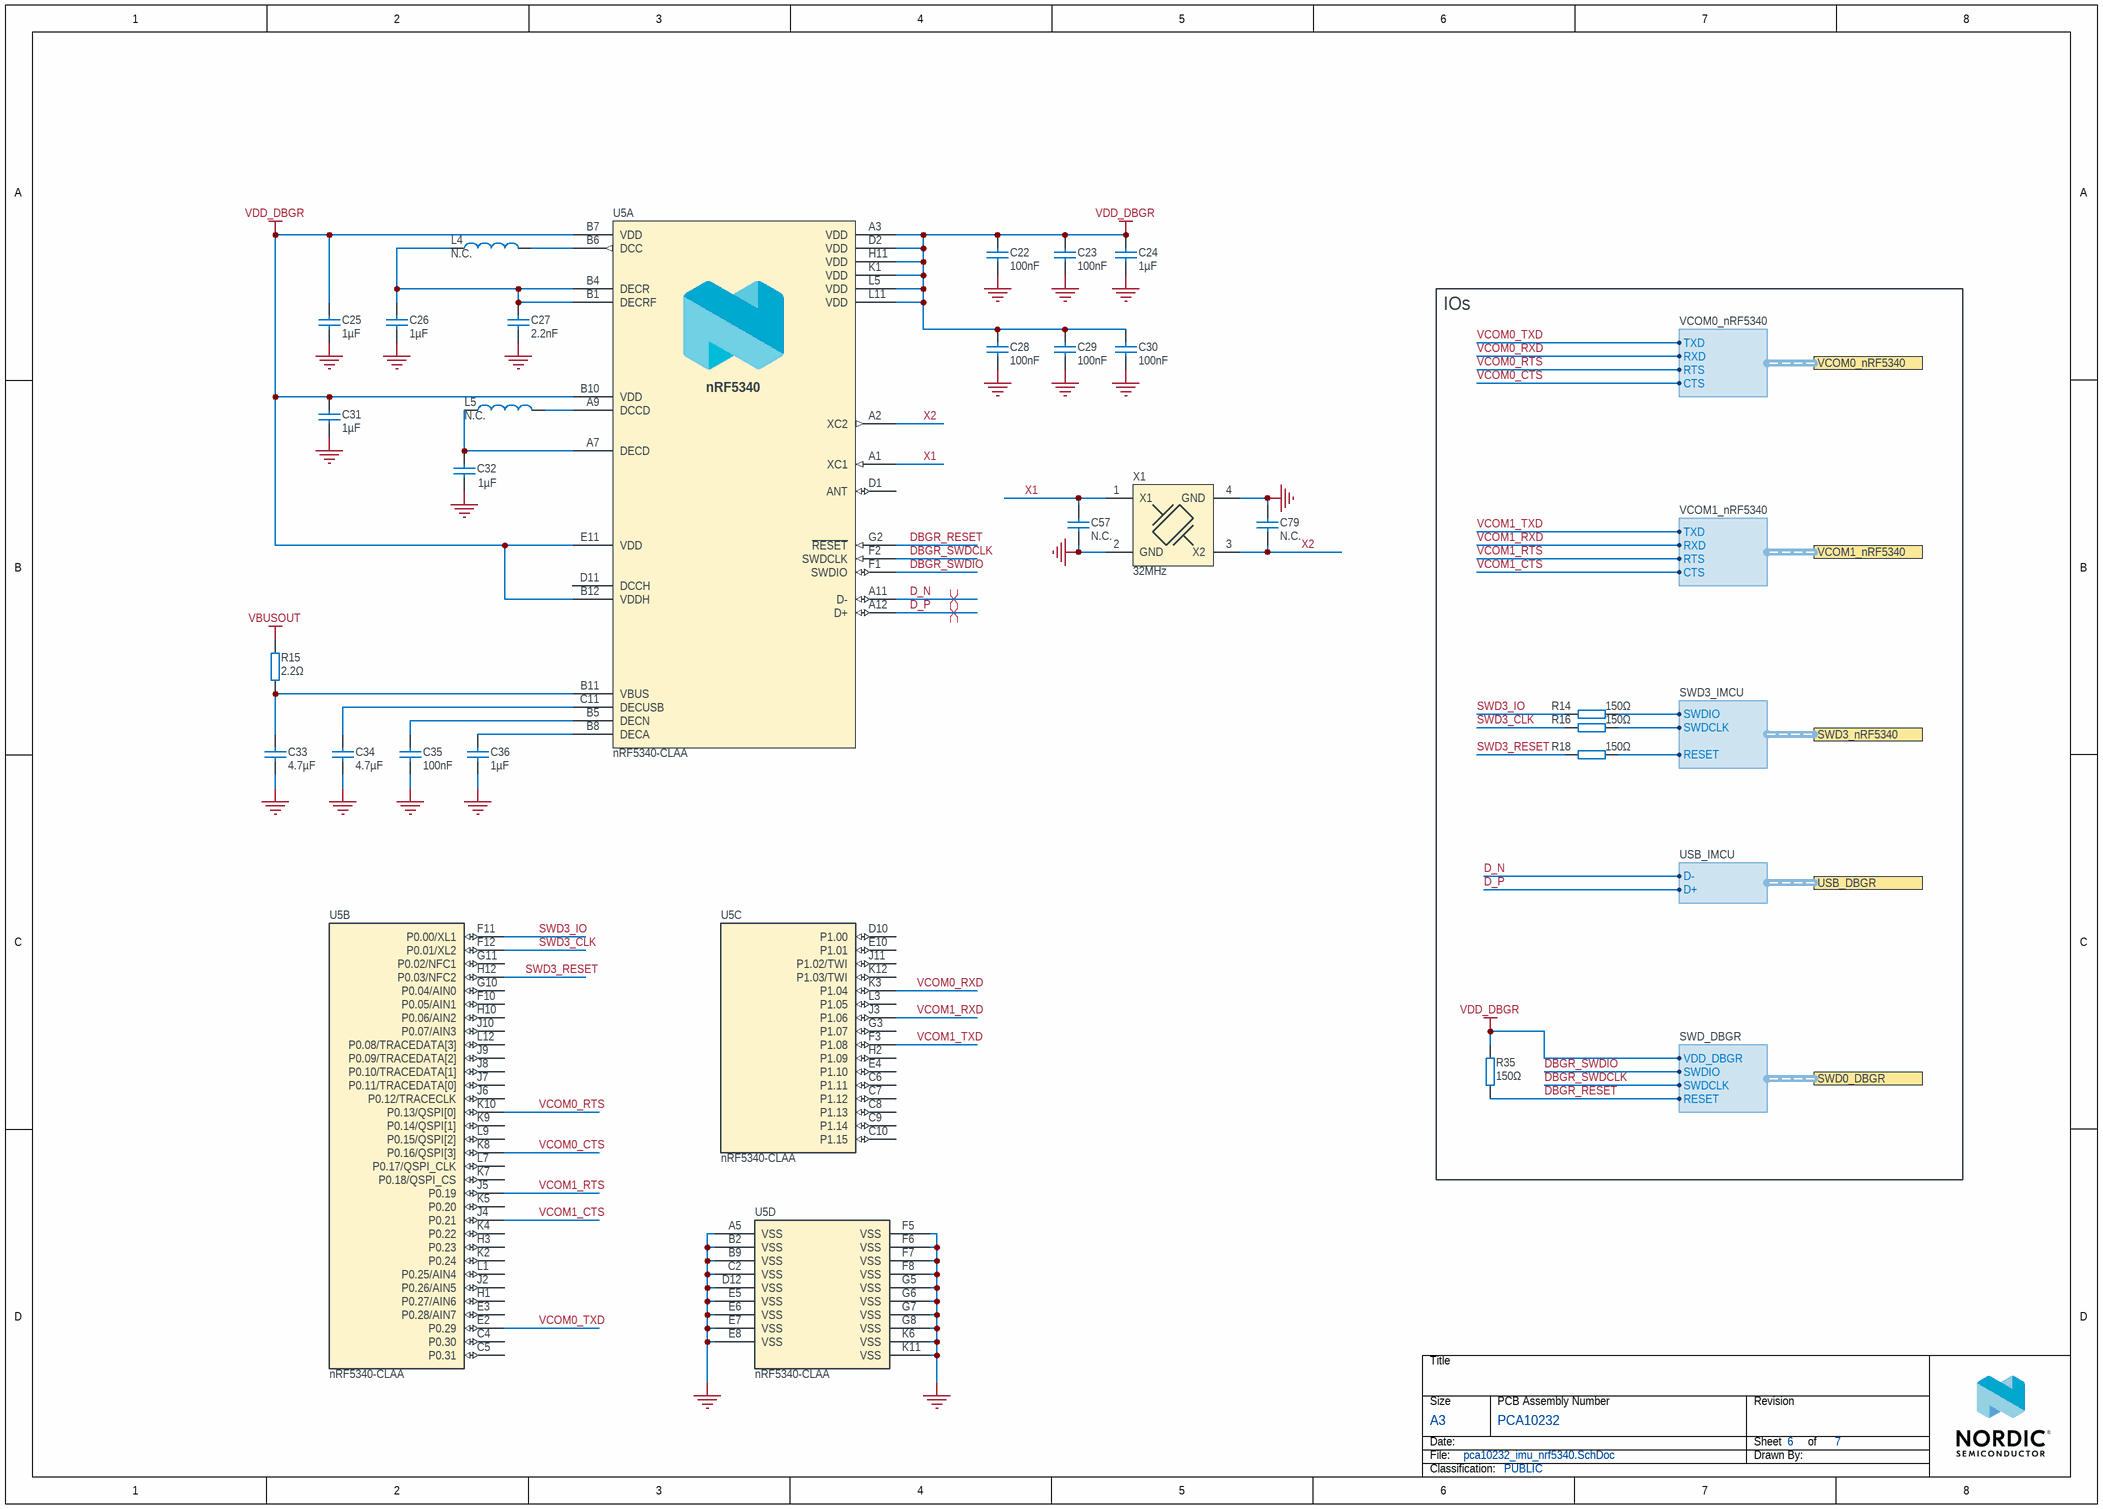
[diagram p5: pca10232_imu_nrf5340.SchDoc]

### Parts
C22  100nF  [0201_0.25D]
C23  100nF  [0201_0.25D]
C24  1µF  [0201_0.25D]
C25  1µF  [0201_0.25D]
C26  1µF  [0201_0.25D]
C27  2.2nF  [0201_0.25D]
C28  100nF  [0201_0.25D]
C29  100nF  [0201_0.25D]
C30  100nF  [0201_0.25D]
C31  1µF  [0201_0.25D]
C32  1µF  [0201_0.25D]
C33  4.7µF  [0402C_0.4D]
C34  4.7µF  [0402C_0.4D]
C35  100nF  [0201_0.25D]
C36  1µF  [0201_0.25D]
C57  N.C.  [0201_0.25D]
C79  N.C.  [0201_0.25D]
L4  N.C.  [0603L_0.6D]
L5  N.C.  [0603L_0.6D]
R14  150Ω  [0201_0.25D]
R15  2.2Ω  [0402R_0.4D]
R16  150Ω  [0201_0.25D]
R18  150Ω  [0201_0.25D]
R35  150Ω  [0201_0.25D]
U5  nRF5340-CLAA  [BGA95C35P12X11_437X397X50]  (parts A,B,C,D of 4)
X1  32MHz  [2016]

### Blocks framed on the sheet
IOs: R14 R16 R18 R35

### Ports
SWD0_DBGR (harness SWD_DBGR), SWD3_nRF5340 (harness SWD3_IMCU), USB_DBGR (harness USB_IMCU), VCOM0_nRF5340 (harness VCOM0_nRF5340), VCOM1_nRF5340 (harness VCOM1_nRF5340)

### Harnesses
USB_IMCU: D+, D-
VCOM0_nRF5340: RTS, CTS, RXD, TXD
VCOM1_nRF5340: RTS, CTS, RXD, TXD
SWD3_IMCU: SWDIO, SWDCLK, RESET
SWD_DBGR: SWDCLK, SWDIO, RESET, VDD_DBGR

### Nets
GND: C22.1 C23.1 C24.1 C25.1 C26.1 C27.1 C28.1 C29.1 C30.1 C31.1 C32.1 C33.1 C34.1 C35.1 C36.1 C57.1 C79.2 U5.A5(VSS) U5.B2(VSS) U5.B9(VSS) U5.C2(VSS) U5.D12(VSS) U5.E5(VSS) U5.E6(VSS) U5.E7(VSS) U5.E8(VSS) U5.F5(VSS) U5.F6(VSS) U5.F7(VSS) U5.F8(VSS) U5.G5(VSS) U5.G6(VSS) U5.G7(VSS) U5.G8(VSS) U5.K6(VSS) U5.K11(VSS) X1.2(GND) X1.4(GND)
VBUSOUT: R15.2
VDD_DBGR: C22.2 C23.2 C24.2 C25.2 C28.2 C29.2 C30.2 C31.2 R35.1 U5.A3(VDD) U5.B7(VDD) U5.B10(VDD) U5.B12(VDDH) U5.D2(VDD) U5.E11(VDD) U5.H11(VDD) U5.K1(VDD) U5.L5(VDD) U5.L11(VDD) ; port SWD0_DBGR.VDD_DBGR
D_N: U5.A11(D-) ; port USB_DBGR.D-
D_P: U5.A12(D+) ; port USB_DBGR.D+
DBGR_RESET: R35.2 U5.G2(~{RESET}) ; port SWD0_DBGR.RESET
DBGR_SWDCLK: U5.F2(SWDCLK) ; port SWD0_DBGR.SWDCLK
DBGR_SWDIO: U5.F1(SWDIO) ; port SWD0_DBGR.SWDIO
SWD3_CLK: R16.1 U5.F12(P0.01/XL2)
SWD3_IO: R14.1 U5.F11(P0.00/XL1)
SWD3_RESET: R18.1 U5.H12(P0.03/NFC2)
VCOM0_CTS: U5.K8(P0.16/QSPI[3]) ; port VCOM0_nRF5340.CTS
VCOM0_RTS: U5.K10(P0.13/QSPI[0]) ; port VCOM0_nRF5340.RTS
VCOM0_RXD: U5.K3(P1.04) ; port VCOM0_nRF5340.RXD
VCOM0_TXD: U5.E2(P0.29) ; port VCOM0_nRF5340.TXD
VCOM1_CTS: U5.J4(P0.21) ; port VCOM1_nRF5340.CTS
VCOM1_RTS: U5.J5(P0.19) ; port VCOM1_nRF5340.RTS
VCOM1_RXD: U5.J3(P1.06) ; port VCOM1_nRF5340.RXD
VCOM1_TXD: U5.F3(P1.08) ; port VCOM1_nRF5340.TXD
X1: C57.2 U5.A1(XC1) X1.1(X1)
X2: C79.1 U5.A2(XC2) X1.3(X2)
NetC26_2: C26.2 C27.2 L4.1 U5.B1(DECRF) U5.B4(DECR)
NetC32_2: C32.2 L5.1 U5.A7(DECD)
NetC33_2: C33.2 R15.1 U5.B11(VBUS)
NetC34_2: C34.2 U5.C11(DECUSB)
NetC35_2: C35.2 U5.B5(DECN)
NetC36_2: C36.2 U5.B8(DECA)
NetL4_2: L4.2 U5.B6(DCC)
NetL5_2: L5.2 U5.A9(DCCD)
NetR14_2: R14.2 ; port SWD3_nRF5340.SWDIO
NetR16_2: R16.2 ; port SWD3_nRF5340.SWDCLK
NetR18_2: R18.2 ; port SWD3_nRF5340.RESET

Not connected (* = marked no-connect by the designer): U5 C4(P0.30) C5(P0.31) C6(P1.11) C7(P1.12) C8(P1.13) C9(P1.14) C10(P1.15) D1(ANT) D10(P1.00) D11(DCCH) E3(P0.28/AIN7) E4(P1.10) E10(P1.01) F10(P0.05/AIN1) G3(P1.07) G10(P0.04/AIN0) G11(P0.02/NFC1) H1(P0.27/AIN6) H2(P1.09) H3(P0.23) H10(P0.06/AIN2) J2(P0.26/AIN5) J6(P0.12/TRACECLK) J7(P0.11/TRACEDATA[0]) J8(P0.10/TRACEDATA[1]) J9(P0.09/TRACEDATA[2]) J10(P0.07/AIN3) J11(P1.02/TWI) K2(P0.24) K4(P0.22) K5(P0.20) K7(P0.18/QSPI_CS) K9(P0.14/QSPI[1]) K12(P1.03/TWI) L1(P0.25/AIN4) L3(P1.05) L7(P0.17/QSPI_CLK) L9(P0.15/QSPI[2]) L12(P0.08/TRACEDATA[3])

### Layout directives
differential pair: D_N, D_P

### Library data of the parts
C22 C23 C28-C30 C35 = 1405001272: as C61 on sheet pca10232_nrf93m1
C24-C26 C31 C32 C36 = 1405005056: 1uF/10V/20%/X5R; Manufacturer Part Number: V105M0201X5R100NXT; Manufacturer: Viiyong
C27 = 1405004274: 2.2nF/16V/10%/X7R; Manufacturer Part Number: CC0201KRX7R7BB222; Manufacturer: Yageo
C33 C34 = 1405005659: 4.7uF/10V/10%/X5R; Manufacturer Part Number: V475K0402X5R100NCT; Manufacturer: Viiyong
C57 C79 = CAP-NBOM: Manufacturer Part Number: N.A.
L4 L5 = L-NBOM: Manufacturer Part Number: N.A.
R14 R16 R18 = 1408006911: 150Ω/1%; Manufacturer Part Number: RC0201FR-07150RL; Manufacturer: Yageo
R15 = 1408001252: 2.2Ω/1%; Manufacturer Part Number: 0402WGF220KTCE; Manufacturer: Uniohm
R35 = 1408001446_1: 150Ω/5%; Manufacturer: Yageo
U5 = nRF5340-CLAA: Multi-protocol Bluetooth Low Energy, IEEE 802.15.4, ANT and 2.4GHz proprietary system-on-chip; Manufacturer: Nordic Semiconductor
X1 = 1413001678: as X2 on sheet pca10232_host_nrf54l15

## Sheet pca10232_connectors.SchDoc: =BoardTitle + ' - Connectors'
size A3; Organization: Nordic Semiconductor; DocumentNumber: 7; Revision: 0.4.0; SheetNumber: 7; SheetTotal: 7; Author: Nordic Semiconductor; CompanyName: Nordic Semiconductor; DrawnBy: Nordic Semiconductor; DocumentSize: A3
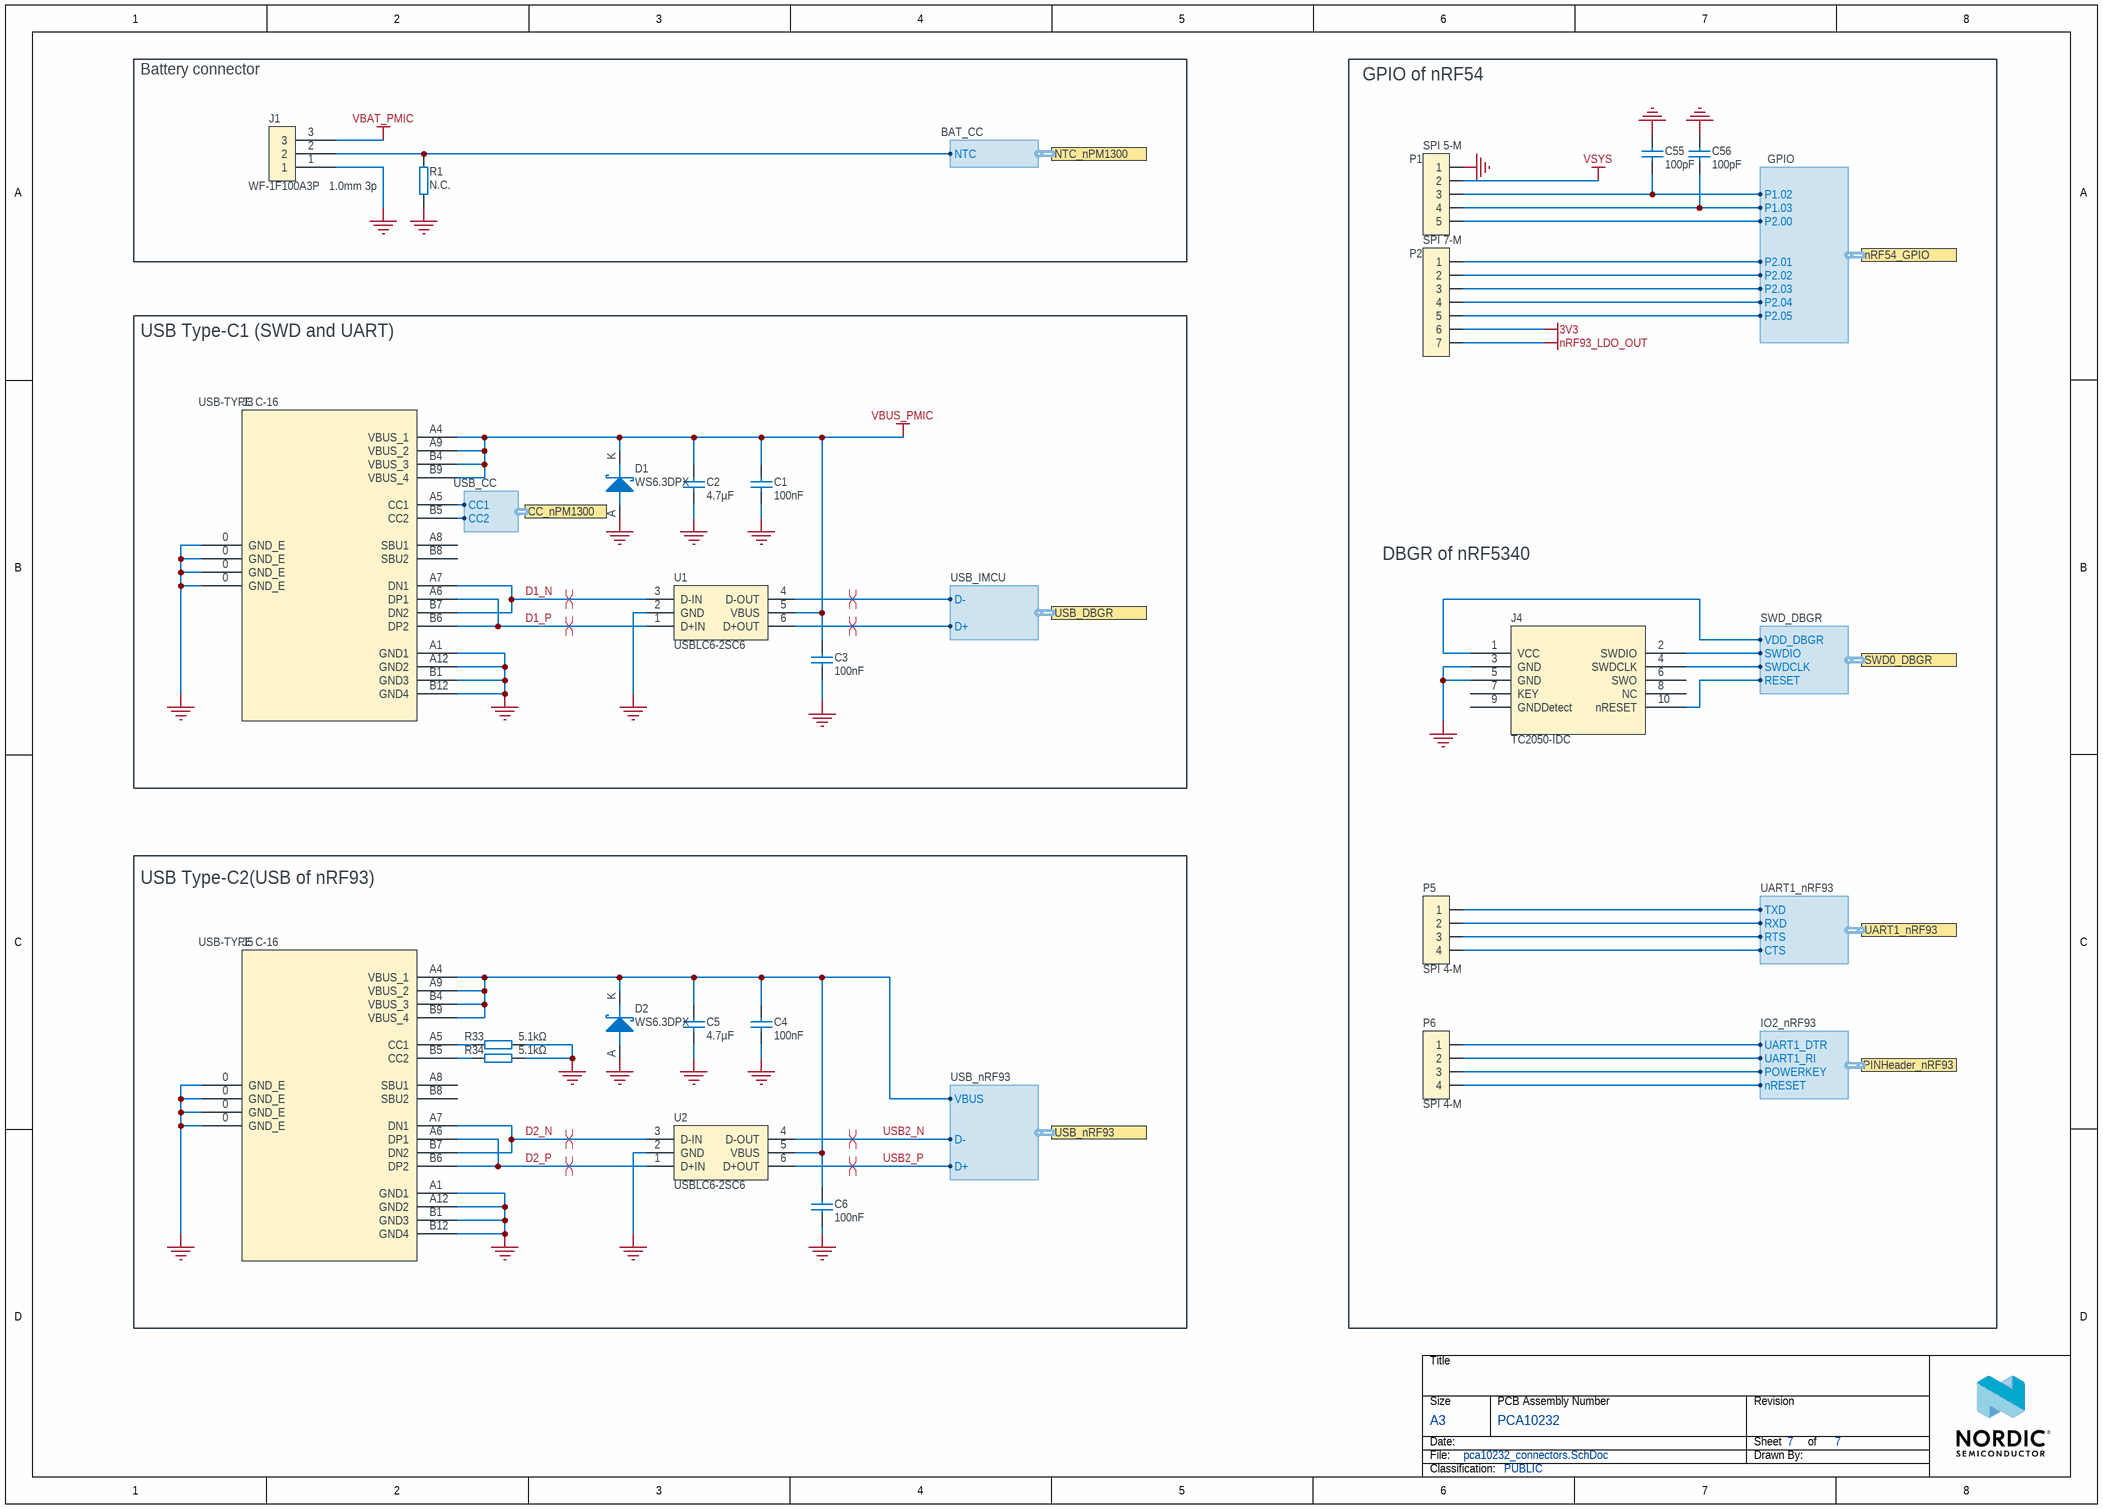
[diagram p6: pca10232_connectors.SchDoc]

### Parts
C1  100nF  [0402C_0.4D]
C2  4.7µF  [0402C_0.4D]
C3  100nF  [0402C_0.4D]
C4  100nF  [0402C_0.4D]
C5  4.7µF  [0402C_0.4D]
C6  100nF  [0402C_0.4D]
C55  100pF  [0402C_0.4D]
C56  100pF  [0402C_0.4D]
D1  WS6.3DPX  [UDFN2(1610)]
D2  WS6.3DPX  [UDFN2(1610)]
J1  WF-1F100A3P   1.0mm 3p  [CON1]
J3  USB-TYPE C-16  [USB-TYPEC-MUP-U20402-1]
J4  TC2050-IDC  [TC2050-IDC-NLFP]
J5  USB-TYPE C-16  [USB-TYPEC-MUP-U20402-1]
P1  SPI 5-M  [SIP 2.54_5_S]
P2  SPI 7-M  [SIP 2.54_7_S]
P5  SPI 4-M  [SIP 2.54_4_S]
P6  SPI 4-M  [SIP 2.54_4_S]
R1  N.C.  [0603R_0.6D]
R33  5.1kΩ  [0201_0.25D]
R34  5.1kΩ  [0201_0.25D]
U1  USBLC6-2SC6  [SOT-23-6P]
U2  USBLC6-2SC6  [SOT-23-6P]

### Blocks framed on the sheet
Battery connector: J1 R1
USB Type-C1 (SWD and UART): C1-C3 D1 J3 U1
USB Type-C2(USB of nRF93): C4-C6 D2 J5 R33 R34 U2

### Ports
CC_nPM1300 (harness USB_CC), nRF54_GPIO (harness GPIO), NTC_nPM1300 (harness BAT_CC), PINHeader_nRF93 (harness IO2_nRF93), SWD0_DBGR (harness SWD_DBGR), UART1_nRF93 (harness UART1_nRF93), USB_DBGR (harness USB_IMCU), USB_nRF93 (harness USB_nRF93)

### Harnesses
USB_IMCU: D-, D+
USB_CC: CC1, CC2
BAT_CC: NTC
SWD_DBGR: SWDCLK, SWDIO, RESET, VDD_DBGR
GPIO: P1.02, P1.03, P2.00, P2.01, P2.02, P2.03, P2.04, P2.05
USB_nRF93: D-, D+, VBUS
UART1_nRF93: RTS, CTS, TXD, RXD
IO2_nRF93: POWERKEY, nRESET, UART1_RI, UART1_DTR

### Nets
3V3: P2.6
GND: C1.1 C2.1 C3.1 C4.1 C5.1 C6.1 C55.1 C56.2 D1.A D2.A J1.1 J3.0(GND_E) J3.A1(GND1) J3.A12(GND2) J3.B1(GND3) J3.B12(GND4) J4.3(GND) J4.5(GND) J5.0(GND_E) J5.A1(GND1) J5.A12(GND2) J5.B1(GND3) J5.B12(GND4) P1.1 R1.1 R33.1 R34.1 U1.2(GND) U2.2(GND)
nRF93_LDO_OUT: P2.7
VBAT_PMIC: J1.3
VBUS_PMIC: C1.2 C2.2 C3.2 D1.K J3.A4(VBUS_1) J3.A9(VBUS_2) J3.B4(VBUS_3) J3.B9(VBUS_4) U1.5(VBUS)
VDD_DBGR: J4.1(VCC) ; port SWD0_DBGR.VDD_DBGR
VSYS: P1.2
CC1: J3.A5(CC1) ; port CC_nPM1300.CC1
CC2: J3.B5(CC2) ; port CC_nPM1300.CC2
D1_N: J3.A7(DN1) J3.B7(DN2) U1.3(D-IN)
D1_P: J3.A6(DP1) J3.B6(DP2) U1.1(D+IN)
D2_N: J5.A7(DN1) J5.B7(DN2) U2.3(D-IN)
D2_P: J5.A6(DP1) J5.B6(DP2) U2.1(D+IN)
D_N: U1.4(D-OUT) ; port USB_DBGR.D-
D_P: U1.6(D+OUT) ; port USB_DBGR.D+
DBGR_RESET: J4.10(nRESET) ; port SWD0_DBGR.RESET
DBGR_SWDCLK: J4.4(SWDCLK) ; port SWD0_DBGR.SWDCLK
DBGR_SWDIO: J4.2(SWDIO) ; port SWD0_DBGR.SWDIO
nRESET: P6.4 ; port PINHeader_nRF93.nRESET
nRF93_VBUS: C4.2 C5.2 C6.2 D2.K J5.A4(VBUS_1) J5.A9(VBUS_2) J5.B4(VBUS_3) J5.B9(VBUS_4) U2.5(VBUS) ; port USB_nRF93.VBUS
NTC: J1.2 R1.2 ; port NTC_nPM1300.NTC
P1.02/NFC1: C55.2 P1.3 ; port nRF54_GPIO.P1.02
P1.03/NFC2: C56.1 P1.4 ; port nRF54_GPIO.P1.03
P1.10: P6.2 ; port PINHeader_nRF93.UART1_RI
P2.07: P6.1 ; port PINHeader_nRF93.UART1_DTR
POWERKEY: P6.3 ; port PINHeader_nRF93.POWERKEY
UART1_CTS: P5.4 ; port UART1_nRF93.CTS
UART1_RTS: P5.3 ; port UART1_nRF93.RTS
USB2_N: U2.4(D-OUT) ; port USB_nRF93.D-
USB2_P: U2.6(D+OUT) ; port USB_nRF93.D+
NetJ5_A5: J5.A5(CC1) R33.2
NetJ5_B5: J5.B5(CC2) R34.2
NetP1_5: P1.5 ; port nRF54_GPIO.P2.00
NetP2_1: P2.1 ; port nRF54_GPIO.P2.01
NetP2_2: P2.2 ; port nRF54_GPIO.P2.02
NetP2_3: P2.3 ; port nRF54_GPIO.P2.03
NetP2_4: P2.4 ; port nRF54_GPIO.P2.04
NetP2_5: P2.5 ; port nRF54_GPIO.P2.05
NetP5_1: P5.1 ; port UART1_nRF93.TXD
NetP5_2: P5.2 ; port UART1_nRF93.RXD

Not connected (* = marked no-connect by the designer): J3 A8(SBU1) B8(SBU2); J4 6(SWO) 7(KEY) 8(NC) 9(GNDDetect); J5 A8(SBU1) B8(SBU2)

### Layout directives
differential pair: D1_N, D1_P, D2_N, D2_P, D_N, D_P, USB2_N, USB2_P

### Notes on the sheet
- GPIO of nRF54
- DBGR of nRF5340

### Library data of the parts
C1 C4 = 1405000464_1: 0.1uF/16V/10%/X7R; Manufacturer Part Number: CL05B104KO5NNNC; Manufacturer: Samsung
C2 C5 = 1405002483: as C17 on sheet pca10232_power
C3 C6 = 1405000041: 0.1uF/16V/10%/X7R; Manufacturer Part Number: CC0402KRX7R7BB104; Manufacturer: Yageo
C55 C56 = 1405000464: as C37 on sheet pca10232_host_nrf54l15
D1 D2 = 1409004319: Manufacturer: Walsin
J3 J5 = 1416004859: USB2.0 TpyeC; Manufacturer Part Number: MUP-U20402-01; Manufacturer: MUP
J4 = 10pin JTAG
R1 = RES-NBOM_0603: Manufacturer Part Number: N.A.
R33 R34 = 1408001425: 5.1KΩ/1%; Manufacturer Part Number: RC0201FR-075K1L; Manufacturer: Yageo
U1 U2 = 1410003301: USB; Manufacturer: ST

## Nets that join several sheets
1V8: pca10232_power (9 pins), pca10232_port_switch (U8.14 U9.14 U10.14)
3V3: pca10232_power (C14.2 C15.2 TP20.1 U3.29), pca10232_host_nrf54l15 (R24.2 R25.2 R26.2), pca10232_nrf93m1 (R47.2 R48.2), pca10232_connectors (P2.6)
GND: pca10232_power (25 pins), pca10232_host_nrf54l15 (42 pins), pca10232_nrf93m1 (105 pins), pca10232_port_switch (6 pins), pca10232_imu_nrf5340 (38 pins), pca10232_connectors (29 pins)
nRF93_LDO_OUT: pca10232_nrf93m1 (5 pins), pca10232_connectors (P2.7)
VBAT_PMIC: pca10232_power (C11.2 U3.19), pca10232_connectors (J1.3)
VBUS_PMIC: pca10232_power (C7.2 U3.21), pca10232_host_nrf54l15 (Q1.G R31.1), pca10232_connectors (9 pins)
VBUSOUT: pca10232_power (C8.2 TP18.1 U3.22), pca10232_imu_nrf5340 (R15.2)
VDD_DBGR: pca10232_power (C13.2 L2.2 TP17.1 U3.32), pca10232_port_switch (R30.2 R60.2), pca10232_imu_nrf5340 (19 pins), pca10232_connectors (J4.1)
VDD_nRF54: pca10232_power (P3.2), pca10232_host_nrf54l15 (15 pins), pca10232_port_switch (R21.1)
VDD_nRF93: pca10232_power (P4.2), pca10232_nrf93m1 (9 pins)
VSYS: pca10232_power (10 pins), pca10232_connectors (P1.2)
BOOT: pca10232_host_nrf54l15 (U6.1), pca10232_nrf93m1 (SB15.1 U11.82)
CC1: pca10232_power (U3.23), pca10232_connectors (J3.A5)
CC2: pca10232_power (U3.24), pca10232_connectors (J3.B5)
D_N: pca10232_imu_nrf5340 (U5.A11), pca10232_connectors (U1.4)
D_P: pca10232_imu_nrf5340 (U5.A12), pca10232_connectors (U1.6)
DBGR_RESET: pca10232_imu_nrf5340 (R35.2 U5.G2), pca10232_connectors (J4.10)
DBGR_SWDCLK: pca10232_imu_nrf5340 (U5.F2), pca10232_connectors (J4.4)
DBGR_SWDIO: pca10232_imu_nrf5340 (U5.F1), pca10232_connectors (J4.2)
NetP1_5: pca10232_host_nrf54l15 (SB8.1), pca10232_connectors (P1.5)
NetP2_1: pca10232_host_nrf54l15 (SB9.1), pca10232_connectors (P2.1)
NetP2_2: pca10232_host_nrf54l15 (SB10.1), pca10232_connectors (P2.2)
NetP2_3: pca10232_host_nrf54l15 (SB11.1), pca10232_connectors (P2.3)
NetP2_4: pca10232_host_nrf54l15 (SB12.1), pca10232_connectors (P2.4)
NetP2_5: pca10232_host_nrf54l15 (SB13.1), pca10232_connectors (P2.5)
NetP5_1: pca10232_nrf93m1 (R62.1), pca10232_port_switch (U9.16), pca10232_connectors (P5.1)
NetP5_2: pca10232_nrf93m1 (R63.1), pca10232_port_switch (U9.4), pca10232_connectors (P5.2)
NetR14_2: pca10232_port_switch (U10.16), pca10232_imu_nrf5340 (R14.2)
NetR16_2: pca10232_port_switch (U10.4), pca10232_imu_nrf5340 (R16.2)
NetR18_2: pca10232_port_switch (U10.8), pca10232_imu_nrf5340 (R18.2)
NetSB3_2: pca10232_power (U3.7), pca10232_host_nrf54l15 (SB3.2)
nRESET: pca10232_nrf93m1 (C74.2 Q6.C SB16.2 U11.15), pca10232_connectors (P6.4)
nRF54_RESET: pca10232_host_nrf54l15 (5 pins), pca10232_port_switch (U10.7)
nRF54_SWDCLK: pca10232_host_nrf54l15 (U6.26), pca10232_port_switch (U10.3)
nRF54_SWDIO: pca10232_host_nrf54l15 (U6.25), pca10232_port_switch (U10.15)
nRF93_VBUS: pca10232_nrf93m1 (U11.61), pca10232_connectors (9 pins)
NTC: pca10232_power (U3.18), pca10232_connectors (J1.2 R1.2)
P0.00: pca10232_host_nrf54l15 (U6.23), pca10232_port_switch (U9.3)
P0.01: pca10232_host_nrf54l15 (U6.24), pca10232_port_switch (U9.15)
P0.02: pca10232_host_nrf54l15 (U6.27), pca10232_port_switch (U9.11)
P0.03: pca10232_host_nrf54l15 (U6.28), pca10232_port_switch (U9.7)
P1.01/XL2: pca10232_power (R10.2 U4.5), pca10232_host_nrf54l15 (U6.2)
P1.02/NFC1: pca10232_host_nrf54l15 (U6.3), pca10232_connectors (C55.2 P1.3)
P1.03/NFC2: pca10232_host_nrf54l15 (U6.4), pca10232_connectors (C56.1 P1.4)
P1.04: pca10232_host_nrf54l15 (U6.5), pca10232_port_switch (U8.3)
P1.05: pca10232_host_nrf54l15 (U6.6), pca10232_port_switch (U8.15)
P1.06: pca10232_host_nrf54l15 (U6.7), pca10232_port_switch (U8.11)
P1.07: pca10232_host_nrf54l15 (U6.8), pca10232_port_switch (U8.7)
P1.10: pca10232_host_nrf54l15 (U6.38), pca10232_nrf93m1 (U11.20), pca10232_connectors (P6.2)
P1.11: pca10232_power (R7.1 U3.14), pca10232_host_nrf54l15 (U6.39)
P1.12: pca10232_host_nrf54l15 (U6.40), pca10232_nrf93m1 (R44.1)
P1.13: pca10232_host_nrf54l15 (U6.41), pca10232_nrf93m1 (R43.1)
P1.14: pca10232_power (R8.2 U3.13), pca10232_host_nrf54l15 (U6.42)
P2.06: pca10232_host_nrf54l15 (U6.17), pca10232_port_switch (R20.2 R21.2 U9.2 U9.10)
P2.07: pca10232_host_nrf54l15 (U6.18), pca10232_nrf93m1 (U11.19), pca10232_connectors (P6.1)
POWERKEY: pca10232_nrf93m1 (C73.2 Q5.C SB1.2 U11.7), pca10232_connectors (P6.3)
UART1_CTS: pca10232_nrf93m1 (U11.23), pca10232_port_switch (U9.12), pca10232_connectors (P5.4)
UART1_RTS: pca10232_nrf93m1 (U11.22), pca10232_port_switch (U9.8), pca10232_connectors (P5.3)
USB2_N: pca10232_nrf93m1 (L10.3 TP11.1), pca10232_connectors (U2.4)
USB2_P: pca10232_nrf93m1 (L10.2 TP10.1), pca10232_connectors (U2.6)
VCOM0_CTS: pca10232_port_switch (U8.12), pca10232_imu_nrf5340 (U5.K8)
VCOM0_RTS: pca10232_port_switch (U8.8), pca10232_imu_nrf5340 (U5.K10)
VCOM0_RXD: pca10232_port_switch (U8.4), pca10232_imu_nrf5340 (U5.K3)
VCOM0_TXD: pca10232_port_switch (U8.16), pca10232_imu_nrf5340 (U5.E2)
VCOM1_CTS: pca10232_port_switch (U9.9), pca10232_imu_nrf5340 (U5.J4)
VCOM1_RTS: pca10232_port_switch (U9.13), pca10232_imu_nrf5340 (U5.J5)
VCOM1_RXD: pca10232_port_switch (U9.1), pca10232_imu_nrf5340 (U5.J3)
VCOM1_TXD: pca10232_port_switch (U9.5), pca10232_imu_nrf5340 (U5.F3)

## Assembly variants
Full assembly: all parts fitted
Release: not fitted C38 C39 C50 C55 C56 C57 C65 C66 C73 C74 C79 C80 L4 L5 R1 R21 R38 R39 R49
